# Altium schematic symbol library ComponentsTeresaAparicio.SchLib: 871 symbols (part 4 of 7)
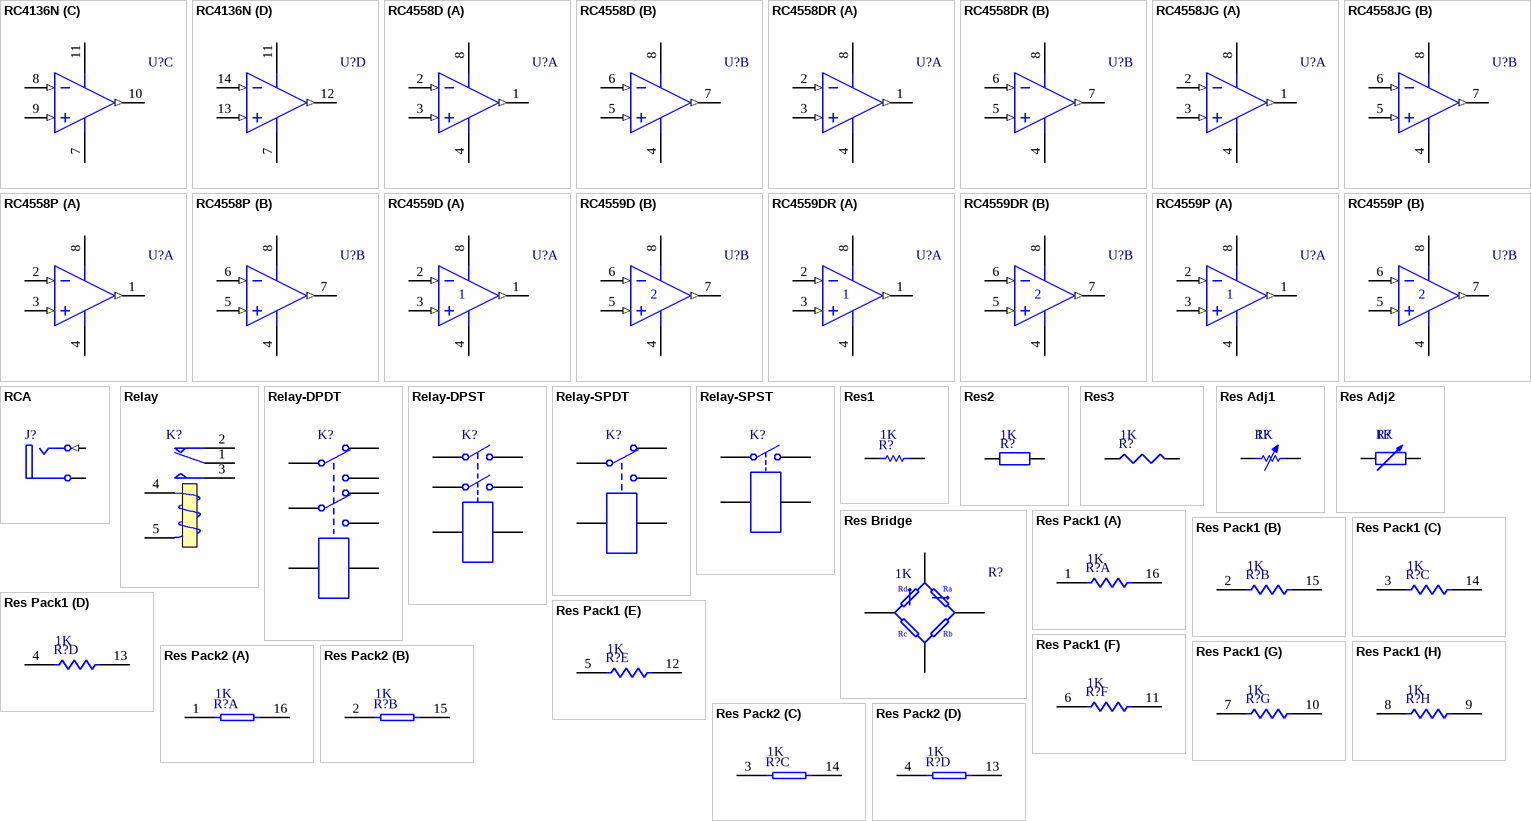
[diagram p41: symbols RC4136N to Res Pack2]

## RC4558P
designator U?
Dual High-Performance Operational Amplifier
footprint P008 (DIP; 8 Leads; Row Spacing 7.62 mm; Pitch 2.54 mm)
3D model P008 (DIP; 8 Leads; Row Spacing 7.62 mm; Pitch 2.54 mm)
pins on every part: 4 V- (power), 8 V+ (power)
part A pins: 1 OUT (out), 2 IN- (in), 3 IN+ (in)
part B pins: 5 IN+ (in), 6 IN- (in), 7 OUT (out)

## RC4559D
designator U?
Dual High-Performance Operational Amplifier
footprint D008_L (SOIC, 8-Leads, Body 4.9x3.9mm, Pitch 1.27mm, IPC High Density)
footprint D008_M (SOIC, 8-Leads, Body 4.9x3.9mm, Pitch 1.27mm, IPC Low Density)
footprint D008_M (SOIC, 8-Leads, Body 4.9x3.9mm, Pitch 1.27mm, IPC Low Density)
3D model D008 (8-Pin Small Outline Integrated Circuit 1.27 mm Pitch)
pins on every part: 4 V- (power), 8 V+ (power)
part A pins: 1 OUT (out), 2 IN- (in), 3 IN+ (in)
part B pins: 5 IN+ (in), 6 IN- (in), 7 OUT (out)

## RC4559DR
designator U?
Dual High-Performance Operational Amplifier
footprint D008_L (SOIC, 8-Leads, Body 4.9x3.9mm, Pitch 1.27mm, IPC High Density)
footprint D008_M (SOIC, 8-Leads, Body 4.9x3.9mm, Pitch 1.27mm, IPC Low Density)
footprint D008_M (SOIC, 8-Leads, Body 4.9x3.9mm, Pitch 1.27mm, IPC Low Density)
3D model D008 (8-Pin Small Outline Integrated Circuit 1.27 mm Pitch)
pins on every part: 4 V- (power), 8 V+ (power)
part A pins: 1 OUT (out), 2 IN- (in), 3 IN+ (in)
part B pins: 5 IN+ (in), 6 IN- (in), 7 OUT (out)

## RC4559P
designator U?
Dual High-Performance Operational Amplifier
footprint P008 (DIP; 8 Leads; Row Spacing 7.62 mm; Pitch 2.54 mm)
3D model P008 (DIP; 8 Leads; Row Spacing 7.62 mm; Pitch 2.54 mm)
pins on every part: 4 V- (power), 8 V+ (power)
part A pins: 1 OUT (out), 2 IN- (in), 3 IN+ (in)
part B pins: 5 IN+ (in), 6 IN- (in), 7 OUT (out)

## RCA
designator J?
RCA Phono Jack, Right Angle, Thru-Hole, Snap-In; PCB_Layout: Complies with manufacturer's recommendation.; DrillAndSlotSize: Corresponds to nominal value.
footprint RCA/4.5-H2 (Two Conductor Jack (RCA), Right Angle, Thru-Hole, Body 10 x 10 x 13 mm (WxTxH))
signal-integrity model RCA
pins: 1A Ground (power) "Outer Shield (Sleeve)", 2B Signal (in) "Center Pin (Plug Tip)"

## Relay
designator K?
SPDT Relay
footprint MODULE5B (DIP; 5 Round Pins; Row Space 15.24 mm; Pitch 2.54 mm)
simulation model SPDTRELAY (Spice Subcircuit)
pins: 1 COM, 2 NC, 3 NO, 4 T1, 5 T2

## Relay-DPDT
designator K?
Dual-Pole Dual-Throw Relay
footprint DIP-P8 (Dual-Pole Dual-Throw Relay; 8 Leads)
simulation model DPDTRELAY (Spice Subcircuit)
pins: 1, 2, 3, 4, 5, 6, 7, 8

## Relay-DPST
designator K?
Dual-Pole Single-Throw Relay
footprint MODULE6 (DIP; 6 Round Pins; Row Space 20.32 mm; Pitch 2.54 mm)
simulation model DPSTRELAY (Spice Subcircuit)
pins: 1, 2, 3, 4, 5, 6

## Relay-SPDT
designator K?
Single-Pole Dual-Throw Relay
footprint MODULE5B (DIP; 5 Round Pins; Row Space 15.24 mm; Pitch 2.54 mm)
simulation model SPDTRELAY (Spice Subcircuit)
pins: 1, 2, 3, 4, 5

## Relay-SPST
designator K?
Single-Pole Single-Throw Relay
footprint MODULE4 (DIP; 4 Round Pins; Row Space 27.94 mm; Pitch 15.24 mm)
simulation model SPSTRELAY (Spice Subcircuit)
pins: 1, 2, 3, 4

## Res1
designator R?  value 1K
Resistor
footprint AXIAL-0.3 (Axial Device, Thru-Hole; 2 Leads; 0.3 in Pin Spacing)
simulation model RESISTOR (Resistor)
signal-integrity model Res
pins: 1, 2

## Res2
designator R?  value 1K
Resistor
footprint AXIAL-0.4 (Axial Device, Thru-Hole; 2 Leads; 0.4 in Pin Spacing)
simulation model RESISTOR (Resistor)
signal-integrity model Res
pins: 1, 2

## Res3
designator R?  value 1K
Resistor
footprint J1-0603 (Chip Resistor, Body 1.6x0.8mm, IPC High Density)
footprint 14-1210 (Chip Resistor, Body 3.2x2.5mm, IPC High Density)
footprint 12Z-2010 (Chip Resistor, Body 5.0x2.5mm, IPC High Density)
footprint RESC6332 (Chip Resistor, Body 6.3x3.2mm, IPC High Density)
simulation model RESISTOR (Resistor)
signal-integrity model Res
pins: 1, 2

## Res Adj1
designator R?  value 1K
Variable Resistor; Set Position: 0.5
footprint AXIAL-0.7 (Axial Device, Thru-Hole; 2 Leads; 0.7 in Pin Spacing)
simulation model VRES (Variable Resistor)
signal-integrity model Res Adj
pins: 1, 2

## Res Adj2
designator R?  value 1K
Variable Resistor; Set Position: 0.5
footprint Pot_10mm (Can; 3 Leads; Pin Circle Dia. 2.54 mm; Lead Dia. 0.48 mm (max))
simulation model VRES (Variable Resistor)
signal-integrity model Res Adj
pins: 2, 3

## Res Bridge
designator R?  value 1K
Resistor Bridge
footprint P04A (TO, Thru-Hole, Vertical, Heatsink Mounted; 4 In-Line Leads; Pitch 2.54 mm)
signal-integrity model Res Bridge
pins: 1, 2, 3, 4

## Res Pack1
designator R?  value 1K
Isolated Resistor Network - Parts; Sim Note: Enter the Resistance value into parameter field.
footprint SOIC16_N (SOIC, 16-Leads, Body 9.9x3.9mm, Pitch 1.27mm, IPC Medium Density)
footprint SOIC16_L (SOIC, 16-Leads, Body 9.9x3.9mm, Pitch 1.27mm, IPC High Density)
footprint SOIC16_M (SOIC, 16-Leads, Body 9.9x3.9mm, Pitch 1.27mm, IPC Low Density)
simulation model RESISTOR (Resistor)
signal-integrity model Res Pack
part A pins: 1, 16
part B pins: 2, 15
part C pins: 3, 14
part D pins: 4, 13
part E pins: 5, 12
part F pins: 6, 11
part G pins: 7, 10
part H pins: 8, 9

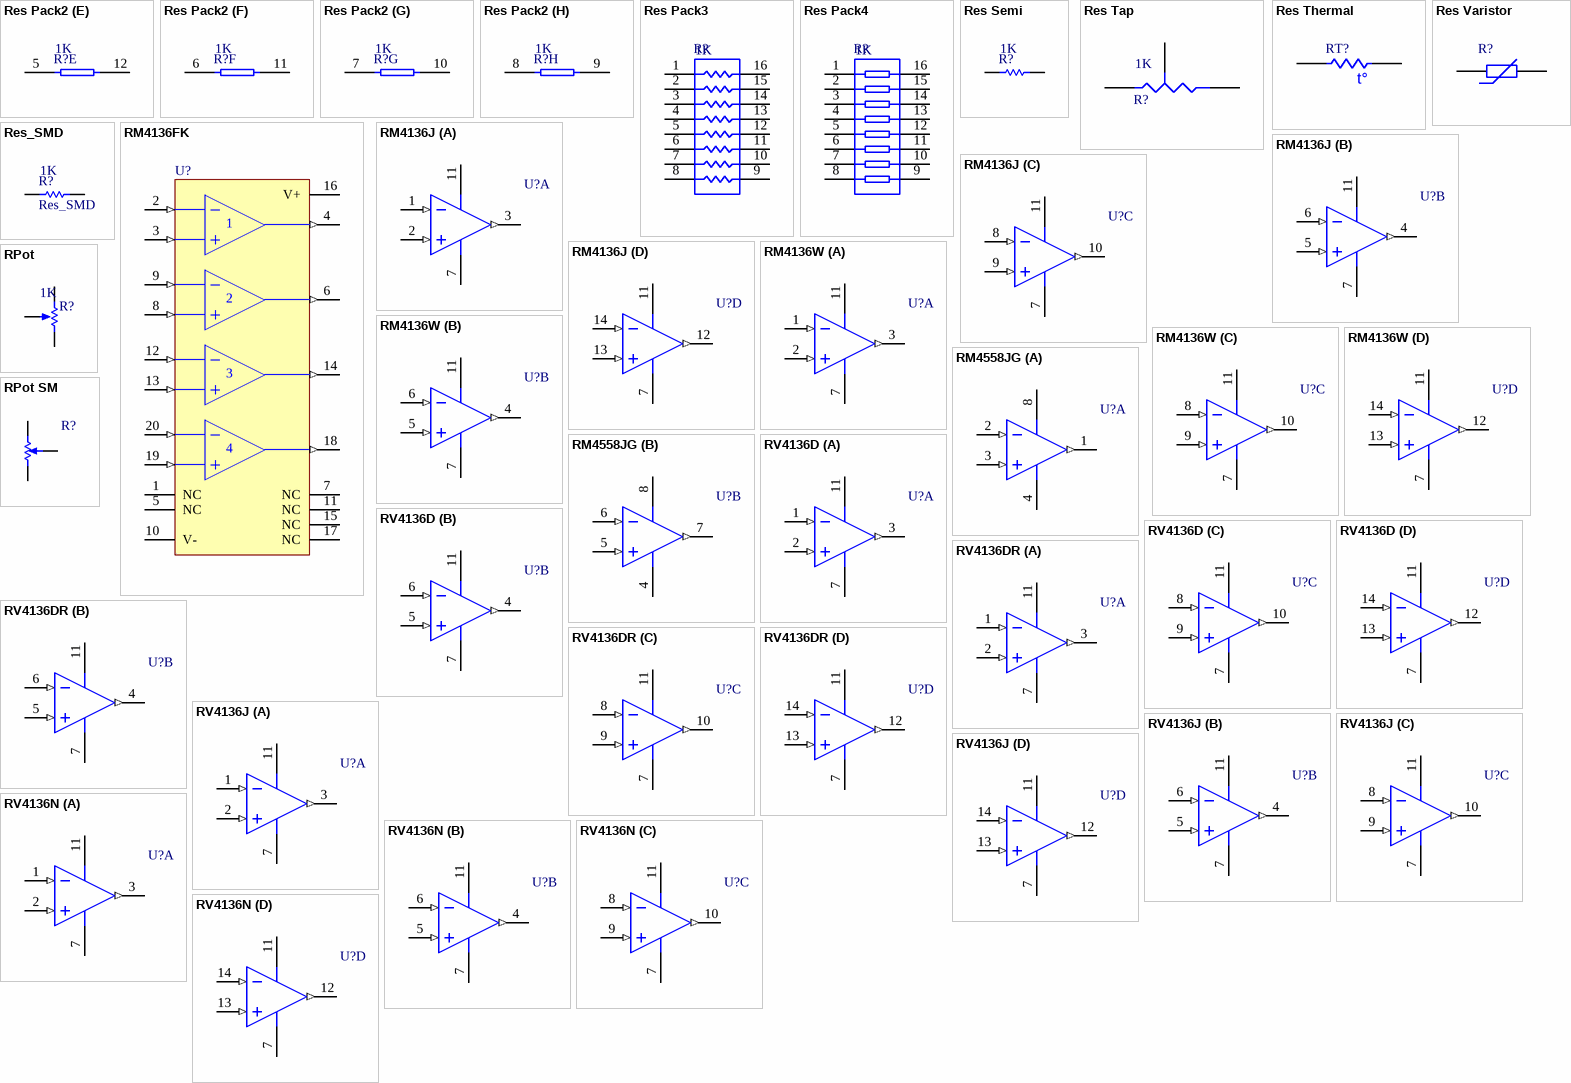
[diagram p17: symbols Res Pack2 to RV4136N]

## Res Pack2
designator R?  value 1K
Isolated Resistor Network - Parts; Sim Note: Enter the Resistance value into parameter field.
footprint DIP-16 (DIP; 16 Leads; Row Spacing 7.62 mm; Pitch 2.54 mm)
simulation model RESISTOR (Resistor)
signal-integrity model Res Pack
part A pins: 1, 16
part B pins: 2, 15
part C pins: 3, 14
part D pins: 4, 13
part E pins: 5, 12
part F pins: 6, 11
part G pins: 7, 10
part H pins: 8, 9

## Res Pack3
designator R?  value 1K
Isolated Resistor Network
footprint SO-16_N (SOIC, 16-Leads, Body 9.9x3.9mm, Pitch 1.27mm, IPC Medium Density)
footprint SO-16_L (SOIC, 16-Leads, Body 9.9x3.9mm, Pitch 1.27mm, IPC High Density)
footprint SO-16_M (SOIC, 16-Leads, Body 9.9x3.9mm, Pitch 1.27mm, IPC Low Density)
simulation model respack_8 (Spice Subcircuit)
pins: 1, 2, 3, 4, 5, 6, 7, 8, 9, 10, 11, 12, 13, 14, 15, 16

## Res Pack4
designator R?  value 1K
Isolated Resistor Network
footprint SSOP16_N (SOP, 16-Leads, Body 6.2x5.3mm, Pitch 0.65mm, IPC Medium Density)
footprint SSOP16_L (SOP, 16-Leads, Body 6.2x5.3mm, Pitch 0.65mm, IPC High Density)
footprint SSOP16_M (SOP, 16-Leads, Body 6.2x5.3mm, Pitch 0.65mm, IPC Low Density)
simulation model respack_8 (Spice Subcircuit)
pins: 1, 2, 3, 4, 5, 6, 7, 8, 9, 10, 11, 12, 13, 14, 15, 16

## Res Semi
designator R?  value 1K
Semiconductor Resistor
footprint AXIAL-0.5 (Axial Device, Thru-Hole; 2 Leads; 0.5 in Pin Spacing)
simulation model RES (Semiconductor Resistor)
signal-integrity model Res Semi
pins: 1, 2

## Res Tap
designator R?  value 1K
Tapped Resistor; Sim Note: Enter the Resistance value and the set point into parameter fields.; Set Position: 0.5
footprint VR3 (Thru-Hole; 3 Leads)
simulation model POT (Potentiometer)
signal-integrity model Res Tap
pins: 1 A, 2 B, 3 TAP

## Res Thermal
designator RT?
Thermistor
footprint 6-0805_N (Chip Resistor, Body 2.0x1.2mm, IPC Medium Density)
footprint 6-0805_L (Chip Resistor, Body 2.0x1.2mm, IPC High Density)
footprint 6-0805_M (Chip Resistor, Body 2.0x1.2mm, IPC Low Density)
pins: 1, 2

## Res Varistor
designator R?
Varistor (Voltage-Sensitive Resistor)
footprint 6-0805_N (Chip Resistor, Body 2.0x1.2mm, IPC Medium Density)
footprint 6-0805_L (Chip Resistor, Body 2.0x1.2mm, IPC High Density)
footprint 6-0805_M (Chip Resistor, Body 2.0x1.2mm, IPC Low Density)
pins: 1, 2

## Res_SMD
designator R?  value 1K
Resistor
footprint ERA-0805 (Chip Resistor; Body 2 x 1.3 mm (LxW typ))
simulation model RESISTOR (Resistor)
signal-integrity model 0805
pins: 1, 2

## RM4136FK
designator U?
Quad High-Performance Operational Amplifier
footprint FK020 (Leadless Chip Carrier; 20 Terminals; Body 8.9 x 8.9 mm)
pins: 1 NC, 2 IN- (in), 3 IN+ (in), 4 OUT (out), 5 NC, 6 OUT (out), 7 NC, 8 IN+ (in), 9 IN- (in), 10 V- (power), 11 NC, 12 IN- (in), 13 IN+ (in), 14 OUT (out), 15 NC, 16 V+ (power), 17 NC, 18 OUT (out), 19 IN+ (in), 20 IN- (in)

## RM4136J
designator U?
Quad High-Performance Operational Amplifier
footprint J014 (DIP; 14 Leads; Row Spacing 7.62 mm; Pitch 2.54 mm)
3D model J014 (DIP; 14 Leads; Row Spacing 7.62 mm; Pitch 2.54 mm)
pins on every part: 7 V- (power), 11 V+ (power)
part A pins: 1 IN- (in), 2 IN+ (in), 3 OUT (out)
part B pins: 4 OUT (out), 5 IN+ (in), 6 IN- (in)
part C pins: 8 IN- (in), 9 IN+ (in), 10 OUT (out)
part D pins: 12 OUT (out), 13 IN+ (in), 14 IN- (in)

## RM4136W
designator U?
Quad High-Performance Operational Amplifier
footprint W014 (DFP; 14 Leads; Body 9.9 x 6.6 mm (LxW max); Pitch 1.27 mm)
3D model W014 (DFP; 14 Leads; Body 9.9 x 6.6 mm (LxW max); Pitch 1.27 mm)
pins on every part: 7 V- (power), 11 V+ (power)
part A pins: 1 IN- (in), 2 IN+ (in), 3 OUT (out)
part B pins: 4 OUT (out), 5 IN+ (in), 6 IN- (in)
part C pins: 8 IN- (in), 9 IN+ (in), 10 OUT (out)
part D pins: 12 OUT (out), 13 IN+ (in), 14 IN- (in)

## RM4558JG
designator U?
Dual High-Performance Operational Amplifier
footprint JG008 (DIP; 8 Leads; Row Spacing 7.62 mm; Pitch 2.54 mm)
3D model JG008 (DIP; 8 Leads; Row Spacing 7.62 mm; Pitch 2.54 mm)
pins on every part: 4 V- (power), 8 V+ (power)
part A pins: 1 OUT (out), 2 IN- (in), 3 IN+ (in)
part B pins: 5 IN+ (in), 6 IN- (in), 7 OUT (out)

## RPot
designator R?  value 1K
Potentiometer; Sim Note: Enter the Resistance value and the set point into parameter fields.; Set Position: 0.5
footprint VR5 (Thru-Hole; 3 Leads)
simulation model POT (Potentiometer)
pins: 1 TOP, 2 BOT, 3 TAP
1 alternate drawing of the same symbol

## RPot SM
designator R?
Square Trimming Potentiometer
footprint POT4MM-2 (Square Trimming Potentiometer)
pins: CCW -, CW +, W
1 alternate drawing of the same symbol

## RV4136D
designator U?
Quad High-Performance Operational Amplifier
footprint D014_N (SOIC, 14-Leads, Body 8.7x3.9mm, Pitch 1.27mm, IPC Medium Density)
footprint D014_L (SOIC, 14-Leads, Body 8.7x3.9mm, Pitch 1.27mm, IPC High Density)
footprint D014_M (SOIC, 14-Leads, Body 8.7x3.9mm, Pitch 1.27mm, IPC Low Density)
3D model D014 (14-Pin Small Outline Integrated Circuit 1.27 mm Pitch)
pins on every part: 7 V- (power), 11 V+ (power)
part A pins: 1 IN- (in), 2 IN+ (in), 3 OUT (out)
part B pins: 4 OUT (out), 5 IN+ (in), 6 IN- (in)
part C pins: 8 IN- (in), 9 IN+ (in), 10 OUT (out)
part D pins: 12 OUT (out), 13 IN+ (in), 14 IN- (in)

## RV4136DR
designator U?
Quad High-Performance Operational Amplifier
footprint D014_N (SOIC, 14-Leads, Body 8.7x3.9mm, Pitch 1.27mm, IPC Medium Density)
footprint D014_L (SOIC, 14-Leads, Body 8.7x3.9mm, Pitch 1.27mm, IPC High Density)
footprint D014_M (SOIC, 14-Leads, Body 8.7x3.9mm, Pitch 1.27mm, IPC Low Density)
3D model D014 (14-Pin Small Outline Integrated Circuit 1.27 mm Pitch)
pins on every part: 7 V- (power), 11 V+ (power)
part A pins: 1 IN- (in), 2 IN+ (in), 3 OUT (out)
part B pins: 4 OUT (out), 5 IN+ (in), 6 IN- (in)
part C pins: 8 IN- (in), 9 IN+ (in), 10 OUT (out)
part D pins: 12 OUT (out), 13 IN+ (in), 14 IN- (in)

## RV4136J
designator U?
Quad High-Performance Operational Amplifier
footprint J014 (DIP; 14 Leads; Row Spacing 7.62 mm; Pitch 2.54 mm)
3D model J014 (DIP; 14 Leads; Row Spacing 7.62 mm; Pitch 2.54 mm)
pins on every part: 7 V- (power), 11 V+ (power)
part A pins: 1 IN- (in), 2 IN+ (in), 3 OUT (out)
part B pins: 4 OUT (out), 5 IN+ (in), 6 IN- (in)
part C pins: 8 IN- (in), 9 IN+ (in), 10 OUT (out)
part D pins: 12 OUT (out), 13 IN+ (in), 14 IN- (in)

## RV4136N
designator U?
Quad High-Performance Operational Amplifier; ComponentAvailability: Obsolete
footprint N014 (DIP; 14 Leads; Row Spacing 7.62 mm; Pitch 2.54 mm)
3D model N014 (DIP; 14 Leads; Row Spacing 7.62 mm; Pitch 2.54 mm)
pins on every part: 7 V- (power), 11 V+ (power)
part A pins: 1 IN- (in), 2 IN+ (in), 3 OUT (out)
part B pins: 4 OUT (out), 5 IN+ (in), 6 IN- (in)
part C pins: 8 IN- (in), 9 IN+ (in), 10 OUT (out)
part D pins: 12 OUT (out), 13 IN+ (in), 14 IN- (in)

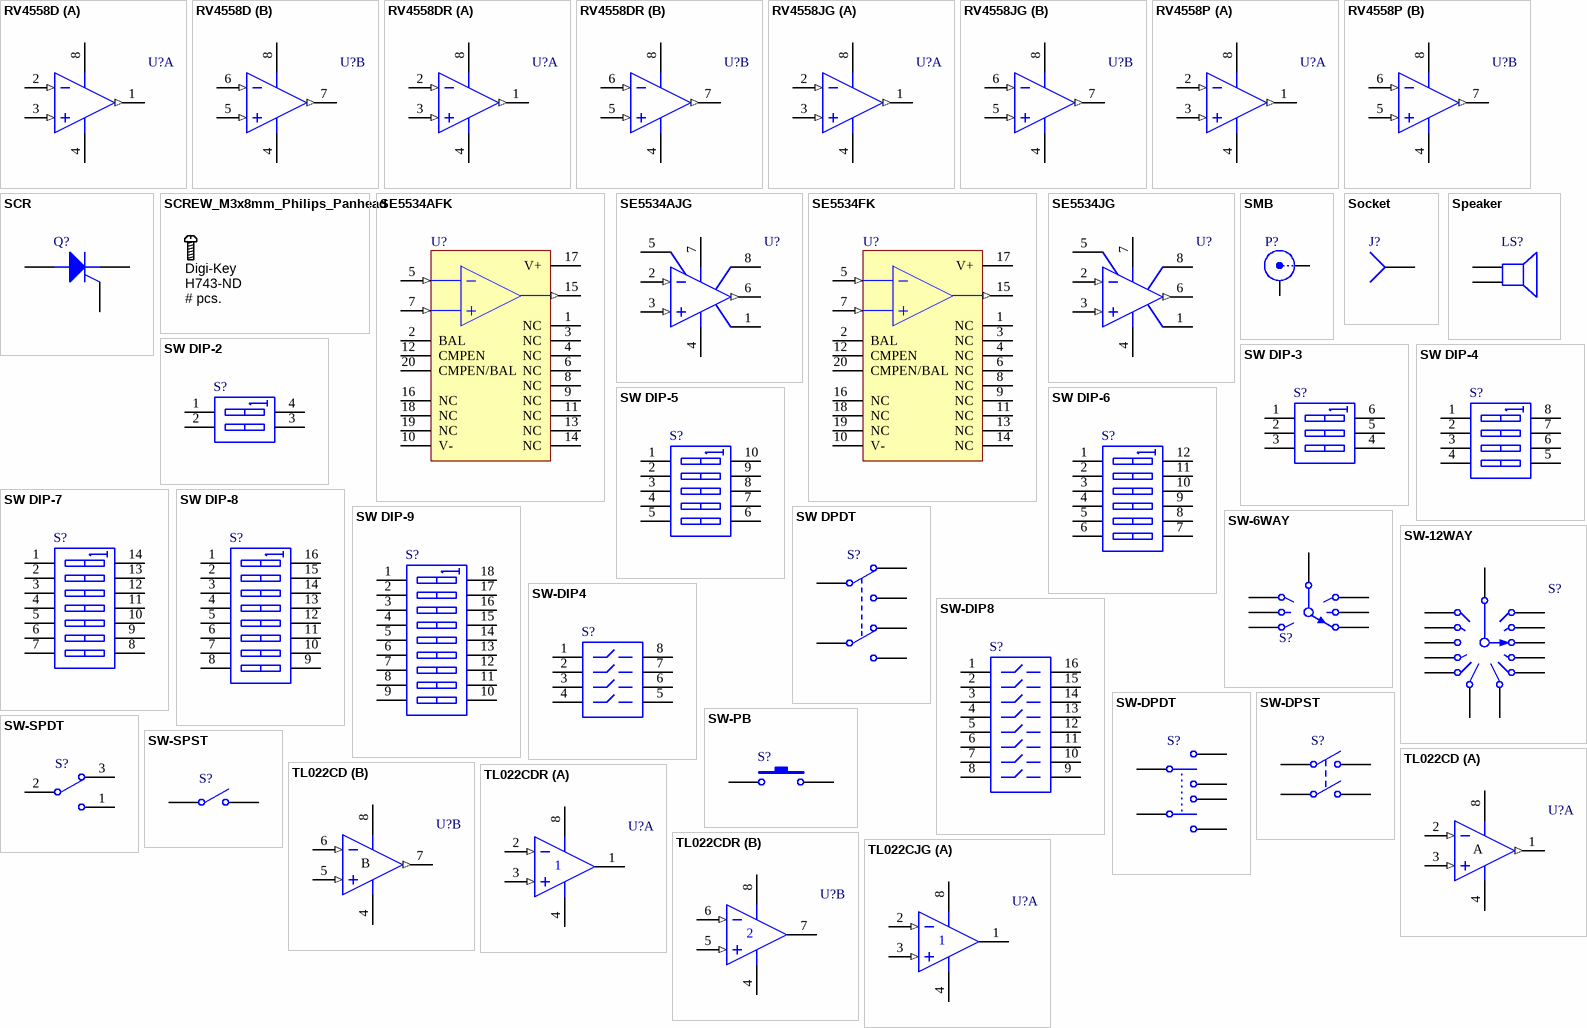
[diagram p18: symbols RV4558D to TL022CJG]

## RV4558D
designator U?
Dual High-Performance Operational Amplifier; ComponentAvailability: Obsolete
footprint D008_L (SOIC, 8-Leads, Body 4.9x3.9mm, Pitch 1.27mm, IPC High Density)
footprint D008_M (SOIC, 8-Leads, Body 4.9x3.9mm, Pitch 1.27mm, IPC Low Density)
footprint D008_M (SOIC, 8-Leads, Body 4.9x3.9mm, Pitch 1.27mm, IPC Low Density)
3D model D008 (8-Pin Small Outline Integrated Circuit 1.27 mm Pitch)
pins on every part: 4 V- (power), 8 V+ (power)
part A pins: 1 OUT (out), 2 IN- (in), 3 IN+ (in)
part B pins: 5 IN+ (in), 6 IN- (in), 7 OUT (out)

## RV4558DR
designator U?
Dual High-Performance Operational Amplifier; ComponentAvailability: Obsolete
footprint D008_L (SOIC, 8-Leads, Body 4.9x3.9mm, Pitch 1.27mm, IPC High Density)
footprint D008_M (SOIC, 8-Leads, Body 4.9x3.9mm, Pitch 1.27mm, IPC Low Density)
footprint D008_M (SOIC, 8-Leads, Body 4.9x3.9mm, Pitch 1.27mm, IPC Low Density)
3D model D008 (8-Pin Small Outline Integrated Circuit 1.27 mm Pitch)
pins on every part: 4 V- (power), 8 V+ (power)
part A pins: 1 OUT (out), 2 IN- (in), 3 IN+ (in)
part B pins: 5 IN+ (in), 6 IN- (in), 7 OUT (out)

## RV4558JG
designator U?
Dual High-Performance Operational Amplifier
footprint JG008 (DIP; 8 Leads; Row Spacing 7.62 mm; Pitch 2.54 mm)
3D model JG008 (DIP; 8 Leads; Row Spacing 7.62 mm; Pitch 2.54 mm)
pins on every part: 4 V- (power), 8 V+ (power)
part A pins: 1 OUT (out), 2 IN- (in), 3 IN+ (in)
part B pins: 5 IN+ (in), 6 IN- (in), 7 OUT (out)

## RV4558P
designator U?
Dual High-Performance Operational Amplifier; ComponentAvailability: Obsolete
footprint P008 (DIP; 8 Leads; Row Spacing 7.62 mm; Pitch 2.54 mm)
3D model P008 (DIP; 8 Leads; Row Spacing 7.62 mm; Pitch 2.54 mm)
pins on every part: 4 V- (power), 8 V+ (power)
part A pins: 1 OUT (out), 2 IN- (in), 3 IN+ (in)
part B pins: 5 IN+ (in), 6 IN- (in), 7 OUT (out)

## SCR
designator Q?
Silicon Controlled Rectifier
footprint TO-220-AB (TO, Thru-Hole, Vertical, Heatsink Mounted; 3 In-Line Leads; Pitch 2.54 mm)
simulation model SCR (Spice Subcircuit)
pins: 1 A, 2 G, 3 K

## SCREW_M3x8mm_Philips_Panhead
designator *, comment # pcs.  Supplier 1: Digi-Key  Supplier Part Number 1: H743-ND  (mechanical)
SCREW MACHINE METRIC PH M3X8MM; Manufacturer 1: B&F Fastener Supply; Manufacturer Part Number 1: MPMS 003 0008 PH; Screw Head Type: Phillips Panhead; Thread Size: M3; Head Height: 0.090" (2.29mm); Plating: Zinc; SCDType: undef
footprint Screw

## SE5534AFK
designator U?
Low-Noise Operational Amplifier
footprint FK020 (Leadless Chip Carrier; 20 Terminals; Body 8.9 x 8.9 mm)
pins: 1 NC, 2 BAL, 3 NC, 4 NC, 5 IN- (in), 6 NC, 7 IN+ (in), 8 NC, 9 NC, 10 V- (power), 11 NC, 12 CMPEN, 13 NC, 14 NC, 15 OUT (out), 16 NC, 17 V+ (power), 18 NC, 19 NC, 20 CMPEN/BAL

## SE5534AJG
designator U?
Low-Noise Operational Amplifier
footprint JG008 (DIP; 8 Leads; Row Spacing 7.62 mm; Pitch 2.54 mm)
3D model JG008 (DIP; 8 Leads; Row Spacing 7.62 mm; Pitch 2.54 mm)
pins: 1 BAL, 2 IN- (in), 3 IN+ (in), 4 V- (power), 5 CMPEN, 6 OUT (out), 7 V+ (power), 8 COMP/BAL

## SE5534FK
designator U?
Low-Noise Operational Amplifier
footprint FK020 (Leadless Chip Carrier; 20 Terminals; Body 8.9 x 8.9 mm)
pins: 1 NC, 2 BAL, 3 NC, 4 NC, 5 IN- (in), 6 NC, 7 IN+ (in), 8 NC, 9 NC, 10 V- (power), 11 NC, 12 CMPEN, 13 NC, 14 NC, 15 OUT (out), 16 NC, 17 V+ (power), 18 NC, 19 NC, 20 CMPEN/BAL

## SE5534JG
designator U?
Low-Noise Operational Amplifier
footprint JG008 (DIP; 8 Leads; Row Spacing 7.62 mm; Pitch 2.54 mm)
3D model JG008 (DIP; 8 Leads; Row Spacing 7.62 mm; Pitch 2.54 mm)
pins: 1 BAL, 2 IN- (in), 3 IN+ (in), 4 V- (power), 5 CMPEN, 6 OUT (out), 7 V+ (power), 8 COMP/BAL

## SMB
designator P?
SMB Straight Connector
footprint SMB_V-RJ45 (Connector; SMB Straight)
signal-integrity model Connector
pins: 1 X, 2 Y

## Socket
designator J?
Socket
footprint PIN1 (Connector; Socket)
signal-integrity model Connector
pins: 1

## Speaker
designator LS?
Loudspeaker
footprint PIN2 (Loudspeaker; 2 Leads)
pins: 1, 2

## SW DIP-2
designator S?
DIP Switch, 2 Position, SPST
footprint DIP-4 (DIP; 4 Leads; Row Spacing 7.62 mm; Pitch 2.54 mm)
simulation model dpsw2 (Spice Subcircuit)
pins: 1 A1, 2 A2, 3 B2, 4 B1

## SW DIP-3
designator S?
DIP Switch, 3 Position, SPST
footprint DIP-6 (DIP; 6 Leads; Row Spacing 7.62 mm; Pitch 2.54 mm)
simulation model dpsw3 (Spice Subcircuit)
pins: 1 A1, 2 A2, 3 A3, 4 B3, 5 B2, 6 B1

## SW DIP-4
designator S?
DIP Switch, 4 Position, SPST
footprint SO8_N (SOIC, 8-Leads, Body 4.9x3.9mm, Pitch 1.27mm, IPC Medium Density)
footprint SO8_L (SOIC, 8-Leads, Body 4.9x3.9mm, Pitch 1.27mm, IPC High Density)
footprint SO8_M (SOIC, 8-Leads, Body 4.9x3.9mm, Pitch 1.27mm, IPC Low Density)
simulation model dpsw4 (Spice Subcircuit)
pins: 1 A1, 2 A2, 3 A3, 4 A4, 5 B4, 6 B3, 7 B2, 8 B1

## SW DIP-5
designator S?
DIP Switch, 5 Position, SPST
footprint N10A (DIP; 10 Leads; Row Spacing 7.62 mm; Pitch 2.54 mm)
simulation model dpsw5 (Spice Subcircuit)
pins: 1 A1, 2 A2, 3 A3, 4 A4, 5 A5, 6 B5, 7 B4, 8 B3, 9 B2, 10 B1

## SW DIP-6
designator S?
DIP Switch, 6 Position, SPST
footprint DIP-12/SW (DIP Switch; 12 Leads)
simulation model dpsw6 (Spice Subcircuit)
pins: 1 A1, 2 A2, 3 A3, 4 A4, 5 A5, 6 A6, 7 B6, 8 B5, 9 B4, 10 B3, 11 B2, 12 B1

## SW DIP-7
designator S?
DIP Switch, 7 Position, SPST
footprint DIP-14 (DIP; 14 Leads; Row Spacing 7.62 mm; Pitch 2.54 mm)
simulation model dpsw7 (Spice Subcircuit)
pins: 1 A1, 2 A2, 3 A3, 4 A4, 5 A5, 6 A6, 7 A7, 8 B7, 9 B6, 10 B5, 11 B4, 12 B3, 13 B2, 14 B1

## SW DIP-8
designator S?
DIP Switch, 8 Position, SPST
footprint DIP_SW_8WAY_SMD (DIP Switch; 16 Leads)
simulation model dpsw8 (Spice Subcircuit)
pins: 1 A1, 2 A2, 3 A3, 4 A4, 5 A5, 6 A6, 7 A7, 8 A8, 9 B8, 10 B7, 11 B6, 12 B5, 13 B4, 14 B3, 15 B2, 16 B1

## SW DIP-9
designator S?
DIP Switch, 9 Position, SPST
footprint DIP-18 (DIP; 18 Leads; Row Spacing 7.62 mm; Pitch 2.54 mm)
simulation model dpsw9 (Spice Subcircuit)
pins: 1 A1, 2 A2, 3 A3, 4 A4, 5 A5, 6 A6, 7 A7, 8 A8, 9 A9, 10 B9, 11 B8, 12 B7, 13 B6, 14 B5, 15 B4, 16 B3, 17 B2, 18 B1

## SW DPDT
designator S?
Switch
footprint SOT23-6_N (SOT23, 6-Leads, Body 2.9x1.6mm, Pitch 0.95mm, Lead Span 2.7mm, IPC Medium Density)
footprint SOT23-6_L (SOT23, 6-Leads, Body 2.9x1.6mm, Pitch 0.95mm, Lead Span 2.7mm, IPC High Density)
footprint SOT23-6_M (SOT23, 6-Leads, Body 2.9x1.6mm, Pitch 0.95mm, Lead Span 2.7mm, IPC Low Density)
pins: 1 COMMON1, 2 NC1, 3 NO1, 4 NC2, 5 COMMON2, 6 NO2

## SW-6WAY
designator S?
6 Way Switch
footprint SW-7 (Switch; 7 Leads)
pins: 1, 2, 3, 4, 5, 6, 7

## SW-12WAY
designator S?
12 Way Switch
footprint DIP-13(14) (DIP; 14 Leads (1 Absent); Row Spacing 7.62 mm; Pitch 2.54 mm)
pins: 1, 2, 3, 5, 6, 7, 8, 9, 10, 11, 12, 13, 14

## SW-DIP4
designator S?
DIP Switch
footprint DIP-8 (DIP; 8 Leads; Row Spacing 7.62 mm; Pitch 2.54 mm)
simulation model dpsw4 (Spice Subcircuit)
pins: 1, 2, 3, 4, 5, 6, 7, 8

## SW-DIP8
designator S?
4009 Series DIP Switch, Raised actuator
footprint DIP-16-KEY (DIP; 16 Leads; Row Spacing 7.62 mm; Pitch 2.54 mm)
simulation model dpsw8 (Spice Subcircuit)
pins: 1, 2, 3, 4, 5, 6, 7, 8, 9, 10, 11, 12, 13, 14, 15, 16

## SW-DPDT
designator S?
Double-Pole, Double-Throw Switch
footprint DPDT-6 (Switch; 6 Leads)
pins: 1, 2, 3, 4, 5, 6

## SW-DPST
designator S?
Double-Pole, Single-Throw Switch
footprint DPST-4 (Switch; 4 Leads)
pins: 1 COMMON1, 2 NO1, 3 COMMON2, 4 NO2

## SW-PB
designator S?
Switch
footprint SPST-2 (Switch; 2 Leads)
pins: 1, 2

## SW-SPDT
designator S?
SPDT Subminiature Toggle Switch, Right Angle Mounting, Vertical Actuation
footprint SWITCH_SPDT_SLIDER (TE Connectivity SLS121PC04 SPDT slider)
pins: 1, 2, 3

## SW-SPST
designator S?
Single-Pole, Single-Throw Switch
footprint SPST-2 (Switch; 2 Leads)
pins: 1 COMMON, 2 NO

## TL022CD
designator U?
Dual Low-Power Operational Amplifier
footprint D008_L (SOIC, 8-Leads, Body 4.9x3.9mm, Pitch 1.27mm, IPC High Density)
footprint D008_M (SOIC, 8-Leads, Body 4.9x3.9mm, Pitch 1.27mm, IPC Low Density)
footprint D008_M (SOIC, 8-Leads, Body 4.9x3.9mm, Pitch 1.27mm, IPC Low Density)
3D model D008 (8-Pin Small Outline Integrated Circuit 1.27 mm Pitch)
simulation model TL022C (SUBCKT)
pins on every part: 4 V- (power), 8 V+ (power)
part A pins: 1 OUT (out), 2 IN- (in), 3 IN+ (in)
part B pins: 5 IN+ (in), 6 IN- (in), 7 OUT (out)

## TL022CDR
designator U?
Dual Low-Power Operational Amplifier
footprint D008_L (SOIC, 8-Leads, Body 4.9x3.9mm, Pitch 1.27mm, IPC High Density)
footprint D008_M (SOIC, 8-Leads, Body 4.9x3.9mm, Pitch 1.27mm, IPC Low Density)
footprint D008_M (SOIC, 8-Leads, Body 4.9x3.9mm, Pitch 1.27mm, IPC Low Density)
3D model D008 (8-Pin Small Outline Integrated Circuit 1.27 mm Pitch)
pins on every part: 4 V- (power), 8 V+ (power)
part A pins: 1 OUT (oe), 2 IN- (in), 3 IN+ (in)
part B pins: 5 IN+ (in), 6 IN- (in), 7 OUT (oe)

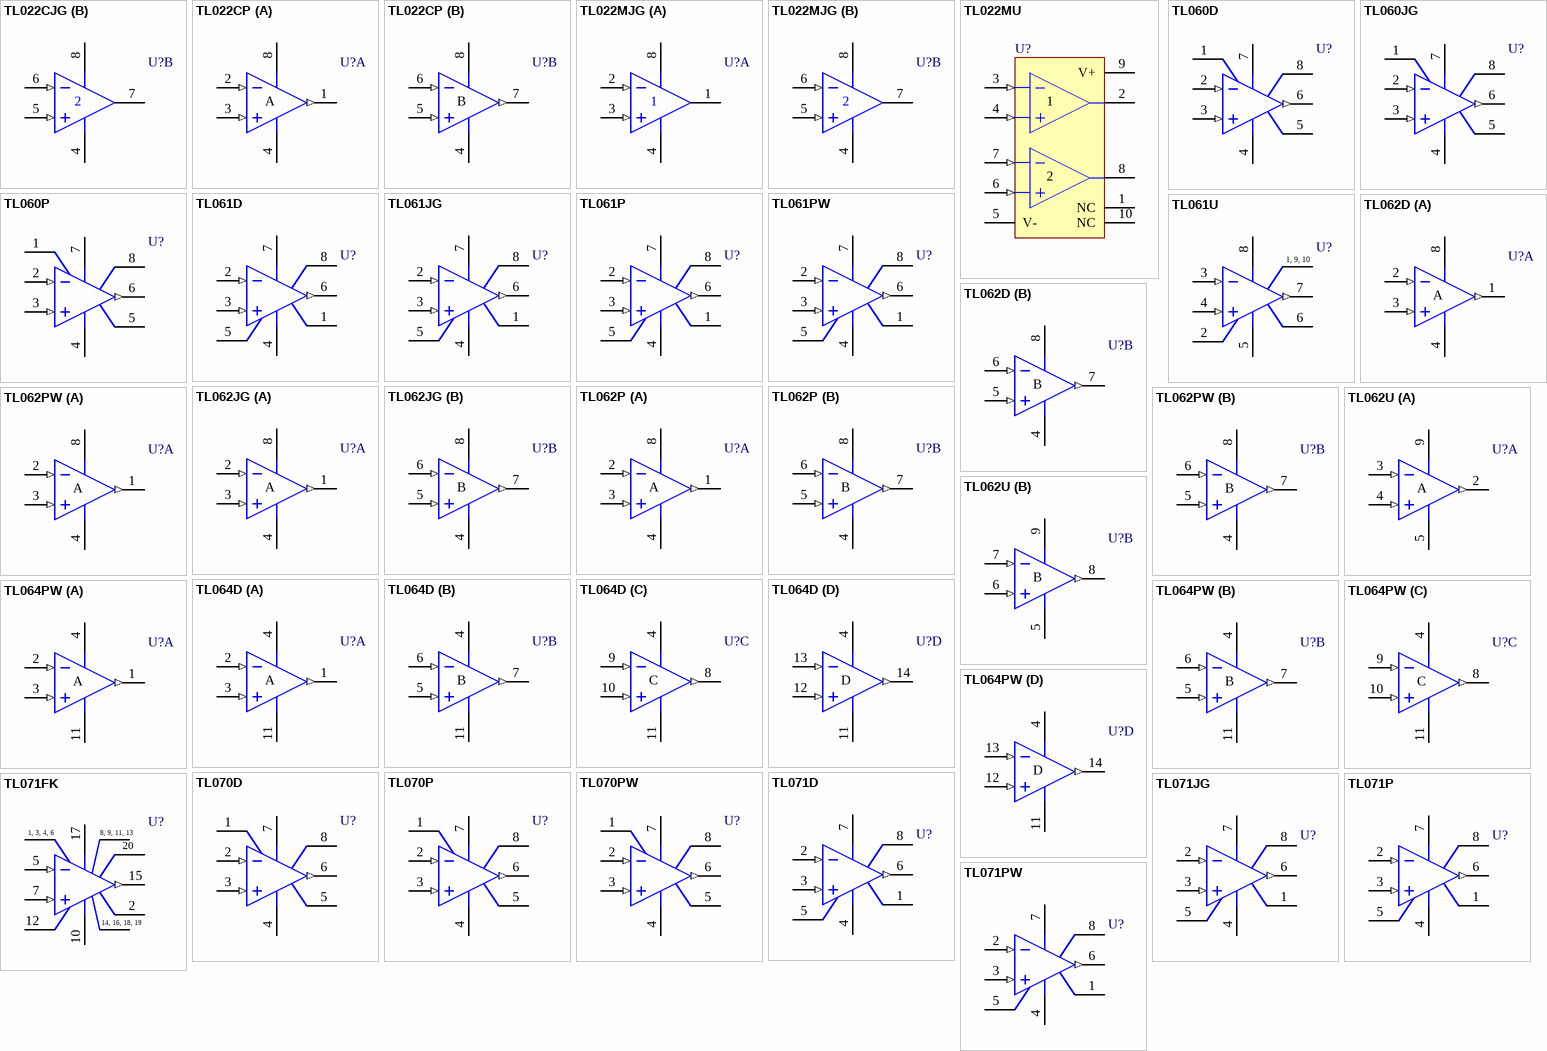
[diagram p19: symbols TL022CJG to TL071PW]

## TL022CJG
designator U?
Dual Low-Power Operational Amplifier
footprint JG008 (DIP; 8 Leads; Row Spacing 7.62 mm; Pitch 2.54 mm)
3D model JG008 (DIP; 8 Leads; Row Spacing 7.62 mm; Pitch 2.54 mm)
pins on every part: 4 V- (power), 8 V+ (power)
part A pins: 1 OUT (oe), 2 IN- (in), 3 IN+ (in)
part B pins: 5 IN+ (in), 6 IN- (in), 7 OUT (oe)

## TL022CP
designator U?
Dual Low-Power Operational Amplifier
footprint P008 (DIP; 8 Leads; Row Spacing 7.62 mm; Pitch 2.54 mm)
3D model P008 (DIP; 8 Leads; Row Spacing 7.62 mm; Pitch 2.54 mm)
simulation model TL022C (SUBCKT)
pins on every part: 4 V- (power), 8 V+ (power)
part A pins: 1 OUT (out), 2 IN- (in), 3 IN+ (in)
part B pins: 5 IN+ (in), 6 IN- (in), 7 OUT (out)

## TL022MJG
designator U?
Dual Low-Power Operational Amplifier
footprint JG008 (DIP; 8 Leads; Row Spacing 7.62 mm; Pitch 2.54 mm)
3D model JG008 (DIP; 8 Leads; Row Spacing 7.62 mm; Pitch 2.54 mm)
pins on every part: 4 V- (power), 8 V+ (power)
part A pins: 1 OUT (oe), 2 IN- (in), 3 IN+ (in)
part B pins: 5 IN+ (in), 6 IN- (in), 7 OUT (oe)

## TL022MU
designator U?
Dual Low-Power Operational Amplifier
footprint U010 (DFP; 10 Leads; Body 7.1 x 6.4 mm (LxW max); Pitch 1.27 mm)
3D model U010 (DFP; 10 Leads; Body 7.1 x 6.4 mm (LxW max); Pitch 1.27 mm)
pins: 1 NC, 2 OUT (oe), 3 IN- (in), 4 IN+ (in), 5 V- (power), 6 IN+ (in), 7 IN- (in), 8 OUT (oe), 9 V+ (power), 10 NC

## TL060D
designator U?
Low-Power JFET-Input Operational Amplifier
footprint D008_L (SOIC, 8-Leads, Body 4.9x3.9mm, Pitch 1.27mm, IPC High Density)
footprint D008_M (SOIC, 8-Leads, Body 4.9x3.9mm, Pitch 1.27mm, IPC Low Density)
footprint D008_M (SOIC, 8-Leads, Body 4.9x3.9mm, Pitch 1.27mm, IPC Low Density)
3D model D008 (8-Pin Small Outline Integrated Circuit 1.27 mm Pitch)
simulation model TL060 (SUBCKT)
pins: 1 BAL1/CMPEN, 2 IN- (in), 3 IN+ (in), 4 V- (power), 5 BAL2, 6 OUT (out), 7 V+ (power), 8 CMPEN

## TL060JG
designator U?
Low-Power JFET-Input Operational Amplifier
footprint JG008 (DIP; 8 Leads; Row Spacing 7.62 mm; Pitch 2.54 mm)
3D model JG008 (DIP; 8 Leads; Row Spacing 7.62 mm; Pitch 2.54 mm)
simulation model TL060 (SUBCKT)
pins: 1 BAL1/CMPEN, 2 IN- (in), 3 IN+ (in), 4 V- (power), 5 BAL2, 6 OUT (out), 7 V+ (power), 8 CMPEN

## TL060P
designator U?
Low-Power JFET-Input Operational Amplifier
footprint P008 (DIP; 8 Leads; Row Spacing 7.62 mm; Pitch 2.54 mm)
3D model P008 (DIP; 8 Leads; Row Spacing 7.62 mm; Pitch 2.54 mm)
simulation model TL060 (SUBCKT)
pins: 1 BAL1/CMPEN, 2 IN- (in), 3 IN+ (in), 4 V- (power), 5 BAL2, 6 OUT (out), 7 V+ (power), 8 CMPEN

## TL061D
designator U?
Low-Power JFET-Input Operational Amplifier; Note: Pin 8 is not connected
footprint D008_L (SOIC, 8-Leads, Body 4.9x3.9mm, Pitch 1.27mm, IPC High Density)
footprint D008_M (SOIC, 8-Leads, Body 4.9x3.9mm, Pitch 1.27mm, IPC Low Density)
footprint D008_M (SOIC, 8-Leads, Body 4.9x3.9mm, Pitch 1.27mm, IPC Low Density)
3D model D008 (8-Pin Small Outline Integrated Circuit 1.27 mm Pitch)
simulation model TL061 (SUBCKT)
pins: 1 OS TRIM, 2 IN- (in), 3 IN+ (in), 4 V- (power), 5 OS TRIM, 6 OUT (out), 7 V+ (power), 8 NC

## TL061JG
designator U?
Low-Power JFET-Input Operational Amplifier; Note: Pin 8 is not connected
footprint JG008 (DIP; 8 Leads; Row Spacing 7.62 mm; Pitch 2.54 mm)
3D model JG008 (DIP; 8 Leads; Row Spacing 7.62 mm; Pitch 2.54 mm)
simulation model TL061 (SUBCKT)
pins: 1 OS TRIM, 2 IN- (in), 3 IN+ (in), 4 V- (power), 5 OS TRIM, 6 OUT (out), 7 V+ (power), 8 NC

## TL061P
designator U?
Low-Power JFET-Input Operational Amplifier; Note: Pin 8 is not connected
footprint P008 (DIP; 8 Leads; Row Spacing 7.62 mm; Pitch 2.54 mm)
3D model P008 (DIP; 8 Leads; Row Spacing 7.62 mm; Pitch 2.54 mm)
simulation model TL061 (SUBCKT)
pins: 1 OS TRIM, 2 IN- (in), 3 IN+ (in), 4 V- (power), 5 OS TRIM, 6 OUT (out), 7 V+ (power), 8 NC

## TL061PW
designator U?
Low-Power JFET-Input Operational Amplifier; Note: Pin 8 is not connected
footprint PW008_N (SOP, 8-Leads, Body 3x4.4mm, Pitch 0.65mm, IPC Medium Density)
footprint PW008_L (SOP, 8-Leads, Body 3x4.4mm, Pitch 0.65mm, IPC High Density)
footprint PW008_M (SOP, 8-Leads, Body 3x4.4mm, Pitch 0.65mm, IPC Low Density)
3D model PW008 (8-Pin Small Outline Package 0.65 mm Pitch)
simulation model TL061 (SUBCKT)
pins: 1 OS TRIM, 2 IN- (in), 3 IN+ (in), 4 V- (power), 5 OS TRIM, 6 OUT (out), 7 V+ (power), 8 NC

## TL061U
designator U?
Low-Power JFET-Input Operational Amplifier; Note: Pin 1,9 and 10 are not connected
footprint U010 (DFP; 10 Leads; Body 7.1 x 6.4 mm (LxW max); Pitch 1.27 mm)
3D model U010 (DFP; 10 Leads; Body 7.1 x 6.4 mm (LxW max); Pitch 1.27 mm)
simulation model TL061 (SUBCKT)
pins: 1 NC, 2 BAL1, 3 IN- (in), 4 IN+ (in), 5 V- (power), 6 BAL2, 7 OUT (out), 8 V+ (power), 9 NC, 10 NC

## TL062D
designator U?
Low-Power JFET-Input Operational Amplifier
footprint D008_L (SOIC, 8-Leads, Body 4.9x3.9mm, Pitch 1.27mm, IPC High Density)
footprint D008_M (SOIC, 8-Leads, Body 4.9x3.9mm, Pitch 1.27mm, IPC Low Density)
footprint D008_M (SOIC, 8-Leads, Body 4.9x3.9mm, Pitch 1.27mm, IPC Low Density)
3D model D008 (8-Pin Small Outline Integrated Circuit 1.27 mm Pitch)
simulation model TL062 (SUBCKT)
pins on every part: 4 V- (power), 8 V+ (power)
part A pins: 1 OUT (out), 2 IN- (in), 3 IN+ (in)
part B pins: 5 IN+ (in), 6 IN- (in), 7 OUT (out)

## TL062JG
designator U?
Low-Power JFET-Input Operational Amplifier
footprint JG008 (DIP; 8 Leads; Row Spacing 7.62 mm; Pitch 2.54 mm)
3D model JG008 (DIP; 8 Leads; Row Spacing 7.62 mm; Pitch 2.54 mm)
simulation model TL062 (SUBCKT)
pins on every part: 4 V- (power), 8 V+ (power)
part A pins: 1 OUT (out), 2 IN- (in), 3 IN+ (in)
part B pins: 5 IN+ (in), 6 IN- (in), 7 OUT (out)

## TL062P
designator U?
Low-Power JFET-Input Operational Amplifier
footprint P008 (DIP; 8 Leads; Row Spacing 7.62 mm; Pitch 2.54 mm)
3D model P008 (DIP; 8 Leads; Row Spacing 7.62 mm; Pitch 2.54 mm)
simulation model TL062 (SUBCKT)
pins on every part: 4 V- (power), 8 V+ (power)
part A pins: 1 OUT (out), 2 IN- (in), 3 IN+ (in)
part B pins: 5 IN+ (in), 6 IN- (in), 7 OUT (out)

## TL062PW
designator U?
Low-Power JFET-Input Operational Amplifier
footprint PW008_N (SOP, 8-Leads, Body 3x4.4mm, Pitch 0.65mm, IPC Medium Density)
footprint PW008_L (SOP, 8-Leads, Body 3x4.4mm, Pitch 0.65mm, IPC High Density)
footprint PW008_M (SOP, 8-Leads, Body 3x4.4mm, Pitch 0.65mm, IPC Low Density)
3D model PW008 (8-Pin Small Outline Package 0.65 mm Pitch)
simulation model TL062 (SUBCKT)
pins on every part: 4 V- (power), 8 V+ (power)
part A pins: 1 OUT (out), 2 IN- (in), 3 IN+ (in)
part B pins: 5 IN+ (in), 6 IN- (in), 7 OUT (out)

## TL062U
designator U?
Low-Power JFET-Input Operational Amplifier; Note: Pins 1 and 10 are not connected or drawn
footprint U010 (DFP; 10 Leads; Body 7.1 x 6.4 mm (LxW max); Pitch 1.27 mm)
3D model U010 (DFP; 10 Leads; Body 7.1 x 6.4 mm (LxW max); Pitch 1.27 mm)
simulation model TL062 (SUBCKT)
pins on every part: 5 V- (power), 9 V+ (power)
part A pins: 2 OUT (out), 3 IN- (in), 4 IN+ (in)
part B pins: 6 IN+ (in), 7 IN- (in), 8 OUT (out)

## TL064D
designator U?
Low-Power JFET-Input Operational Amplifier
footprint D014_N (SOIC, 14-Leads, Body 8.7x3.9mm, Pitch 1.27mm, IPC Medium Density)
footprint D014_L (SOIC, 14-Leads, Body 8.7x3.9mm, Pitch 1.27mm, IPC High Density)
footprint D014_M (SOIC, 14-Leads, Body 8.7x3.9mm, Pitch 1.27mm, IPC Low Density)
3D model D014 (14-Pin Small Outline Integrated Circuit 1.27 mm Pitch)
simulation model TL064 (SUBCKT)
pins on every part: 4 V+ (power), 11 V- (power)
part A pins: 1 OUT (out), 2 IN- (in), 3 IN+ (in)
part B pins: 5 IN+ (in), 6 IN- (in), 7 OUT (out)
part C pins: 8 OUT (out), 9 IN- (in), 10 IN+ (in)
part D pins: 12 IN+ (in), 13 IN- (in), 14 OUT (out)

## TL064PW
designator U?
Low-Power JFET-Input Operational Amplifier
footprint PW014_N (TSOP, 14-Leads, Body 5x4.4mm, Pitch 0.65mm, IPC Medium Density)
footprint PW014_L (TSOP, 14-Leads, Body 5x4.4mm, Pitch 0.65mm, IPC High Density)
footprint PW014_M (TSOP, 14-Leads, Body 5x4.4mm, Pitch 0.65mm, IPC Low Density)
3D model PW014 (14-Pin Thin Small Outline Package 0.65 mm Pitch)
simulation model TL064 (SUBCKT)
pins on every part: 4 V+ (power), 11 V- (power)
part A pins: 1 OUT (out), 2 IN- (in), 3 IN+ (in)
part B pins: 5 IN+ (in), 6 IN- (in), 7 OUT (out)
part C pins: 8 OUT (out), 9 IN- (in), 10 IN+ (in)
part D pins: 12 IN+ (in), 13 IN- (in), 14 OUT (out)

## TL070D
designator U?
JFET-Input Operational Amplifier
footprint D008_L (SOIC, 8-Leads, Body 4.9x3.9mm, Pitch 1.27mm, IPC High Density)
footprint D008_M (SOIC, 8-Leads, Body 4.9x3.9mm, Pitch 1.27mm, IPC Low Density)
footprint D008_M (SOIC, 8-Leads, Body 4.9x3.9mm, Pitch 1.27mm, IPC Low Density)
3D model D008 (8-Pin Small Outline Integrated Circuit 1.27 mm Pitch)
simulation model TL070 (SUBCKT)
pins: 1 BAL1/CMPEN, 2 IN- (in), 3 IN+ (in), 4 V- (power), 5 BAL2, 6 OUT (out), 7 V+ (power), 8 CMPEN

## TL070P
designator U?
JFET-Input Operational Amplifier
footprint P008 (DIP; 8 Leads; Row Spacing 7.62 mm; Pitch 2.54 mm)
3D model P008 (DIP; 8 Leads; Row Spacing 7.62 mm; Pitch 2.54 mm)
simulation model TL070 (SUBCKT)
pins: 1 BAL1/CMPEN, 2 IN- (in), 3 IN+ (in), 4 V- (power), 5 BAL2, 6 OUT (out), 7 V+ (power), 8 CMPEN

## TL070PW
designator U?
JFET-Input Operational Amplifier
footprint PW008_N (SOP, 8-Leads, Body 3x4.4mm, Pitch 0.65mm, IPC Medium Density)
footprint PW008_L (SOP, 8-Leads, Body 3x4.4mm, Pitch 0.65mm, IPC High Density)
footprint PW008_M (SOP, 8-Leads, Body 3x4.4mm, Pitch 0.65mm, IPC Low Density)
3D model PW008 (8-Pin Small Outline Package 0.65 mm Pitch)
simulation model TL070 (SUBCKT)
pins: 1 BAL1/CMPEN, 2 IN- (in), 3 IN+ (in), 4 V- (power), 5 BAL2, 6 OUT (out), 7 V+ (power), 8 CMPEN

## TL071D
designator U?
Low-Noise JFET-Input Operational Amplifier; Note: Pin 8 is not connected
footprint D008_L (SOIC, 8-Leads, Body 4.9x3.9mm, Pitch 1.27mm, IPC High Density)
footprint D008_M (SOIC, 8-Leads, Body 4.9x3.9mm, Pitch 1.27mm, IPC Low Density)
footprint D008_M (SOIC, 8-Leads, Body 4.9x3.9mm, Pitch 1.27mm, IPC Low Density)
3D model D008 (8-Pin Small Outline Integrated Circuit 1.27 mm Pitch)
simulation model TL071 (SUBCKT)
pins: 1 OS TRIM, 2 IN- (in), 3 IN+ (in), 4 V- (power), 5 OS TRIM, 6 OUT (out), 7 V+ (power), 8 NC

## TL071FK
designator U?
Low-Noise JFET-Input Operational Amplifier; Note: Pins 1,3,4,6,8,9,11,14,16,18,19 and 20 are not connected
footprint FK020 (Leadless Chip Carrier; 20 Terminals; Body 8.9 x 8.9 mm)
simulation model TL071 (SUBCKT)
pins: 1 NC, 2 N1/COMP, 3 NC, 4 NC, 5 IN- (in), 6 NC, 7 IN+ (in), 8 NC, 9 NC, 10 V- (power), 11 NC, 12 N2, 13 NC, 14 NC, 15 OUT (out), 16 NC, 17 V+ (power), 18 NC, 19 NC, 20 NC

## TL071JG
designator U?
Low-Noise JFET-Input Operational Amplifier; Note: Pin 8 is not connected
footprint JG008 (DIP; 8 Leads; Row Spacing 7.62 mm; Pitch 2.54 mm)
3D model JG008 (DIP; 8 Leads; Row Spacing 7.62 mm; Pitch 2.54 mm)
simulation model TL071 (SUBCKT)
pins: 1 OS TRIM, 2 IN- (in), 3 IN+ (in), 4 V- (power), 5 OS TRIM, 6 OUT (out), 7 V+ (power), 8 NC

## TL071P
designator U?
Low-Noise JFET-Input Operational Amplifier; Note: Pin 8 is not connected
footprint P008 (DIP; 8 Leads; Row Spacing 7.62 mm; Pitch 2.54 mm)
3D model P008 (DIP; 8 Leads; Row Spacing 7.62 mm; Pitch 2.54 mm)
simulation model TL071 (SUBCKT)
pins: 1 OS TRIM, 2 IN- (in), 3 IN+ (in), 4 V- (power), 5 OS TRIM, 6 OUT (out), 7 V+ (power), 8 NC

## TL071PW
designator U?
Low-Noise JFET-Input Operational Amplifier; Note: Pin 8 is not connected
footprint PW008_N (SOP, 8-Leads, Body 3x4.4mm, Pitch 0.65mm, IPC Medium Density)
footprint PW008_L (SOP, 8-Leads, Body 3x4.4mm, Pitch 0.65mm, IPC High Density)
footprint PW008_M (SOP, 8-Leads, Body 3x4.4mm, Pitch 0.65mm, IPC Low Density)
3D model PW008 (8-Pin Small Outline Package 0.65 mm Pitch)
simulation model TL071 (SUBCKT)
pins: 1 OS TRIM, 2 IN- (in), 3 IN+ (in), 4 V- (power), 5 OS TRIM, 6 OUT (out), 7 V+ (power), 8 NC

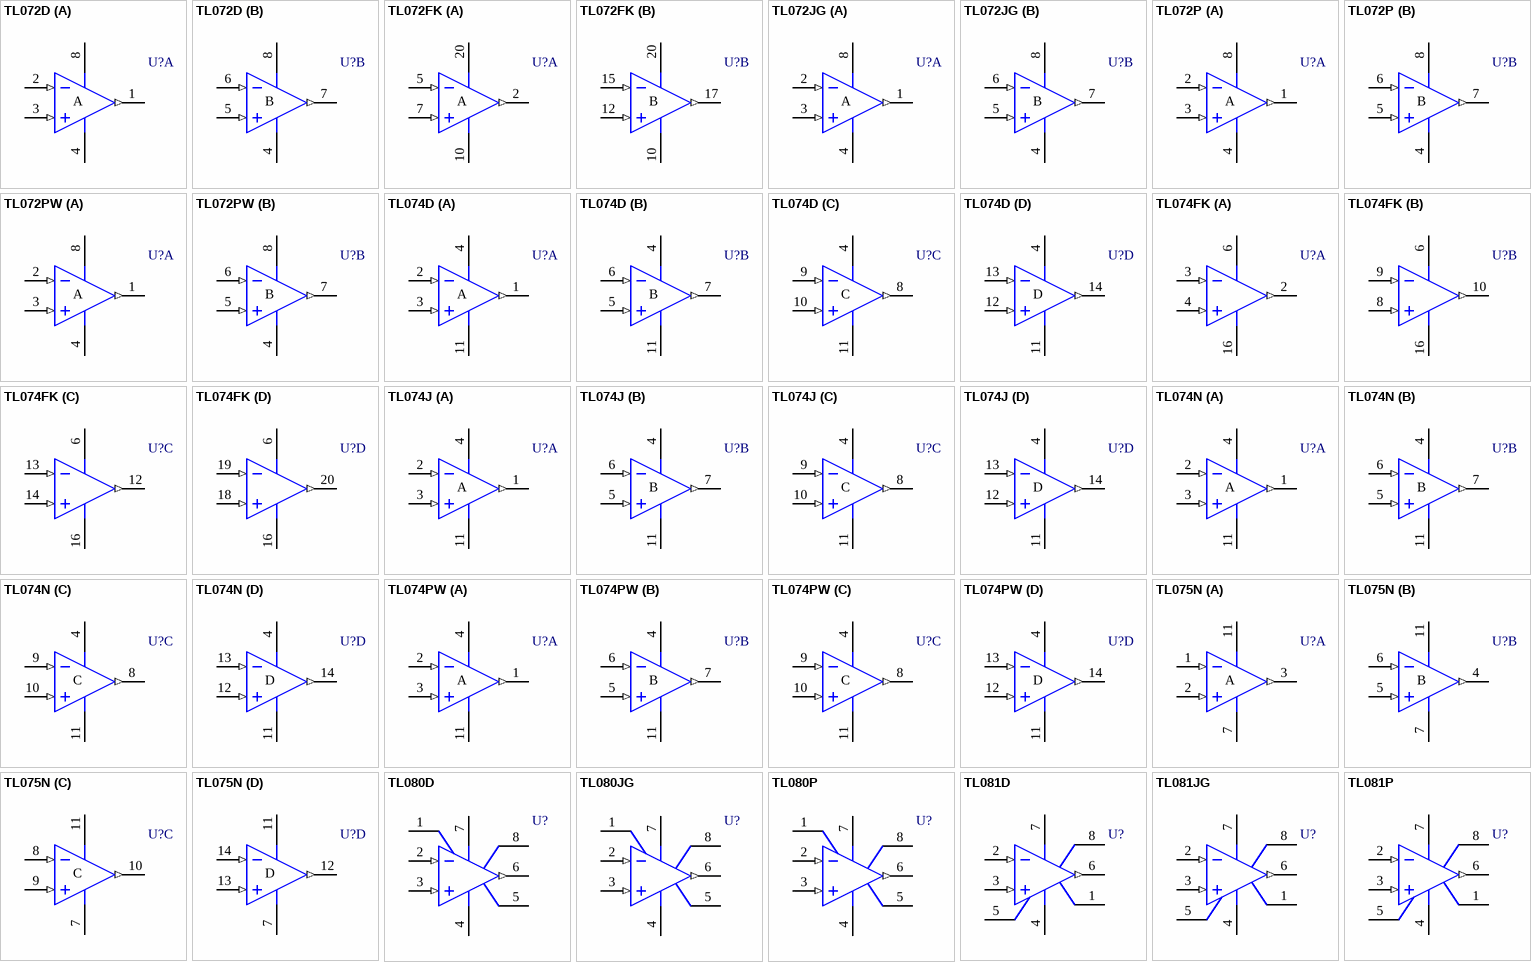
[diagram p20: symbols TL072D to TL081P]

## TL072D
designator U?
Low-Noise JFET-Input Operational Amplifier
footprint D008_L (SOIC, 8-Leads, Body 4.9x3.9mm, Pitch 1.27mm, IPC High Density)
footprint D008_M (SOIC, 8-Leads, Body 4.9x3.9mm, Pitch 1.27mm, IPC Low Density)
footprint D008_M (SOIC, 8-Leads, Body 4.9x3.9mm, Pitch 1.27mm, IPC Low Density)
3D model D008 (8-Pin Small Outline Integrated Circuit 1.27 mm Pitch)
simulation model TL072 (SUBCKT)
pins on every part: 4 V- (power), 8 V+ (power)
part A pins: 1 OUT (out), 2 IN- (in), 3 IN+ (in)
part B pins: 5 IN+ (in), 6 IN- (in), 7 OUT (out)

## TL072FK
designator U?
Low-Noise JFET-Input Operational Amplifier; Note: Pins 1,3,4,6,8,9,11,13,14,16,18 and 19 are not connected or drawn
footprint FK020 (Leadless Chip Carrier; 20 Terminals; Body 8.9 x 8.9 mm)
simulation model TL072 (SUBCKT)
pins on every part: 10 V- (power), 20 V+ (power)
part A pins: 2 OUT (out), 5 IN- (in), 7 IN+ (in)
part B pins: 12 IN+ (in), 15 IN- (in), 17 OUT (out)

## TL072JG
designator U?
Low-Noise JFET-Input Operational Amplifier
footprint JG008 (DIP; 8 Leads; Row Spacing 7.62 mm; Pitch 2.54 mm)
3D model JG008 (DIP; 8 Leads; Row Spacing 7.62 mm; Pitch 2.54 mm)
simulation model TL072 (SUBCKT)
pins on every part: 4 V- (power), 8 V+ (power)
part A pins: 1 OUT (out), 2 IN- (in), 3 IN+ (in)
part B pins: 5 IN+ (in), 6 IN- (in), 7 OUT (out)

## TL072P
designator U?
Low-Noise JFET-Input Operational Amplifier
footprint P008 (DIP; 8 Leads; Row Spacing 7.62 mm; Pitch 2.54 mm)
3D model P008 (DIP; 8 Leads; Row Spacing 7.62 mm; Pitch 2.54 mm)
simulation model TL072 (SUBCKT)
pins on every part: 4 V- (power), 8 V+ (power)
part A pins: 1 OUT (out), 2 IN- (in), 3 IN+ (in)
part B pins: 5 IN+ (in), 6 IN- (in), 7 OUT (out)

## TL072PW
designator U?
Low-Noise JFET-Input Operational Amplifier
footprint PW008_N (SOP, 8-Leads, Body 3x4.4mm, Pitch 0.65mm, IPC Medium Density)
footprint PW008_L (SOP, 8-Leads, Body 3x4.4mm, Pitch 0.65mm, IPC High Density)
footprint PW008_M (SOP, 8-Leads, Body 3x4.4mm, Pitch 0.65mm, IPC Low Density)
3D model PW008 (8-Pin Small Outline Package 0.65 mm Pitch)
simulation model TL072 (SUBCKT)
pins on every part: 4 V- (power), 8 V+ (power)
part A pins: 1 OUT (out), 2 IN- (in), 3 IN+ (in)
part B pins: 5 IN+ (in), 6 IN- (in), 7 OUT (out)

## TL074D
designator U?
Low-Noise JFET-Input Operational Amplifier
footprint D014_N (SOIC, 14-Leads, Body 8.7x3.9mm, Pitch 1.27mm, IPC Medium Density)
footprint D014_L (SOIC, 14-Leads, Body 8.7x3.9mm, Pitch 1.27mm, IPC High Density)
footprint D014_M (SOIC, 14-Leads, Body 8.7x3.9mm, Pitch 1.27mm, IPC Low Density)
3D model D014 (14-Pin Small Outline Integrated Circuit 1.27 mm Pitch)
simulation model TL074 (SUBCKT)
pins on every part: 4 V+ (power), 11 V- (power)
part A pins: 1 OUT (out), 2 IN- (in), 3 IN+ (in)
part B pins: 5 IN+ (in), 6 IN- (in), 7 OUT (out)
part C pins: 8 OUT (out), 9 IN- (in), 10 IN+ (in)
part D pins: 12 IN+ (in), 13 IN- (in), 14 OUT (out)

## TL074FK
designator U?
Low-Noise JFET-Input Operational Amplifier; Note: Pins 1,5,7,11,15 and 17 are not connected and not drawn
footprint FK020 (Leadless Chip Carrier; 20 Terminals; Body 8.9 x 8.9 mm)
simulation model TL074 (SUBCKT)
pins on every part: 6 V+ (power), 16 V- (power)
part A pins: 2 OUT (out), 3 IN- (in), 4 IN+ (in)
part B pins: 8 IN+ (in), 9 IN- (in), 10 OUT (out)
part C pins: 12 OUT (out), 13 IN- (in), 14 IN+ (in)
part D pins: 18 IN+ (in), 19 IN- (in), 20 OUT (out)

## TL074J
designator U?
Low-Noise JFET-Input Operational Amplifier
footprint J014 (DIP; 14 Leads; Row Spacing 7.62 mm; Pitch 2.54 mm)
3D model J014 (DIP; 14 Leads; Row Spacing 7.62 mm; Pitch 2.54 mm)
simulation model TL074 (SUBCKT)
pins on every part: 4 V+ (power), 11 V- (power)
part A pins: 1 OUT (out), 2 IN- (in), 3 IN+ (in)
part B pins: 5 IN+ (in), 6 IN- (in), 7 OUT (out)
part C pins: 8 OUT (out), 9 IN- (in), 10 IN+ (in)
part D pins: 12 IN+ (in), 13 IN- (in), 14 OUT (out)

## TL074N
designator U?
Low-Noise JFET-Input Operational Amplifier
footprint N014 (DIP; 14 Leads; Row Spacing 7.62 mm; Pitch 2.54 mm)
3D model N014 (DIP; 14 Leads; Row Spacing 7.62 mm; Pitch 2.54 mm)
simulation model TL074 (SUBCKT)
pins on every part: 4 V+ (power), 11 V- (power)
part A pins: 1 OUT (out), 2 IN- (in), 3 IN+ (in)
part B pins: 5 IN+ (in), 6 IN- (in), 7 OUT (out)
part C pins: 8 OUT (out), 9 IN- (in), 10 IN+ (in)
part D pins: 12 IN+ (in), 13 IN- (in), 14 OUT (out)

## TL074PW
designator U?
Low-Noise JFET-Input Operational Amplifier
footprint PW014_N (TSOP, 14-Leads, Body 5x4.4mm, Pitch 0.65mm, IPC Medium Density)
footprint PW014_L (TSOP, 14-Leads, Body 5x4.4mm, Pitch 0.65mm, IPC High Density)
footprint PW014_M (TSOP, 14-Leads, Body 5x4.4mm, Pitch 0.65mm, IPC Low Density)
3D model PW014 (14-Pin Thin Small Outline Package 0.65 mm Pitch)
simulation model TL074 (SUBCKT)
pins on every part: 4 V+ (power), 11 V- (power)
part A pins: 1 OUT (out), 2 IN- (in), 3 IN+ (in)
part B pins: 5 IN+ (in), 6 IN- (in), 7 OUT (out)
part C pins: 8 OUT (out), 9 IN- (in), 10 IN+ (in)
part D pins: 12 IN+ (in), 13 IN- (in), 14 OUT (out)

## TL075N
designator U?
Low-Noise Operational Amplifier
footprint N014 (DIP; 14 Leads; Row Spacing 7.62 mm; Pitch 2.54 mm)
3D model N014 (DIP; 14 Leads; Row Spacing 7.62 mm; Pitch 2.54 mm)
simulation model TL075 (SUBCKT)
pins on every part: 7 V- (power), 11 V+ (power)
part A pins: 1 IN- (in), 2 IN+ (in), 3 OUT (out)
part B pins: 4 OUT (out), 5 IN+ (in), 6 IN- (in)
part C pins: 8 IN- (in), 9 IN+ (in), 10 OUT (out)
part D pins: 12 OUT (out), 13 IN+ (in), 14 IN- (in)

## TL080D
designator U?
JFET-Input Operational Amplifier
footprint D008_L (SOIC, 8-Leads, Body 4.9x3.9mm, Pitch 1.27mm, IPC High Density)
footprint D008_M (SOIC, 8-Leads, Body 4.9x3.9mm, Pitch 1.27mm, IPC Low Density)
footprint D008_M (SOIC, 8-Leads, Body 4.9x3.9mm, Pitch 1.27mm, IPC Low Density)
3D model D008 (8-Pin Small Outline Integrated Circuit 1.27 mm Pitch)
simulation model TL080 (SUBCKT)
pins: 1 BAL1/CMPEN, 2 IN- (in), 3 IN+ (in), 4 V- (power), 5 BAL2, 6 OUT (out), 7 V+ (power), 8 CMPEN

## TL080JG
designator U?
JFET-Input Operational Amplifier
footprint JG008 (DIP; 8 Leads; Row Spacing 7.62 mm; Pitch 2.54 mm)
3D model JG008 (DIP; 8 Leads; Row Spacing 7.62 mm; Pitch 2.54 mm)
simulation model TL080 (SUBCKT)
pins: 1 BAL1/CMPEN, 2 IN- (in), 3 IN+ (in), 4 V- (power), 5 BAL2, 6 OUT (out), 7 V+ (power), 8 CMPEN

## TL080P
designator U?
JFET-Input Operational Amplifier
footprint P008 (DIP; 8 Leads; Row Spacing 7.62 mm; Pitch 2.54 mm)
3D model P008 (DIP; 8 Leads; Row Spacing 7.62 mm; Pitch 2.54 mm)
simulation model TL080 (SUBCKT)
pins: 1 BAL1/CMPEN, 2 IN- (in), 3 IN+ (in), 4 V- (power), 5 BAL2, 6 OUT (out), 7 V+ (power), 8 CMPEN

## TL081D
designator U?
JFET-Input Operational Amplifier; Note: Pin 8 is not connected
footprint D008_L (SOIC, 8-Leads, Body 4.9x3.9mm, Pitch 1.27mm, IPC High Density)
footprint D008_M (SOIC, 8-Leads, Body 4.9x3.9mm, Pitch 1.27mm, IPC Low Density)
footprint D008_M (SOIC, 8-Leads, Body 4.9x3.9mm, Pitch 1.27mm, IPC Low Density)
3D model D008 (8-Pin Small Outline Integrated Circuit 1.27 mm Pitch)
simulation model TL081 (SUBCKT)
pins: 1 OS TRIM, 2 IN- (in), 3 IN+ (in), 4 V- (power), 5 OS TRIM, 6 OUT (out), 7 V+ (power), 8 NC

## TL081JG
designator U?
JFET-Input Operational Amplifier; Note: Pin 8 is not connected
footprint JG008 (DIP; 8 Leads; Row Spacing 7.62 mm; Pitch 2.54 mm)
3D model JG008 (DIP; 8 Leads; Row Spacing 7.62 mm; Pitch 2.54 mm)
simulation model TL081 (SUBCKT)
pins: 1 OS TRIM, 2 IN- (in), 3 IN+ (in), 4 V- (power), 5 OS TRIM, 6 OUT (out), 7 V+ (power), 8 NC

## TL081P
designator U?
JFET-Input Operational Amplifier; Note: Pin 8 is not connected
footprint P008 (DIP; 8 Leads; Row Spacing 7.62 mm; Pitch 2.54 mm)
3D model P008 (DIP; 8 Leads; Row Spacing 7.62 mm; Pitch 2.54 mm)
simulation model TL081 (SUBCKT)
pins: 1 OS TRIM, 2 IN- (in), 3 IN+ (in), 4 V- (power), 5 OS TRIM, 6 OUT (out), 7 V+ (power), 8 NC

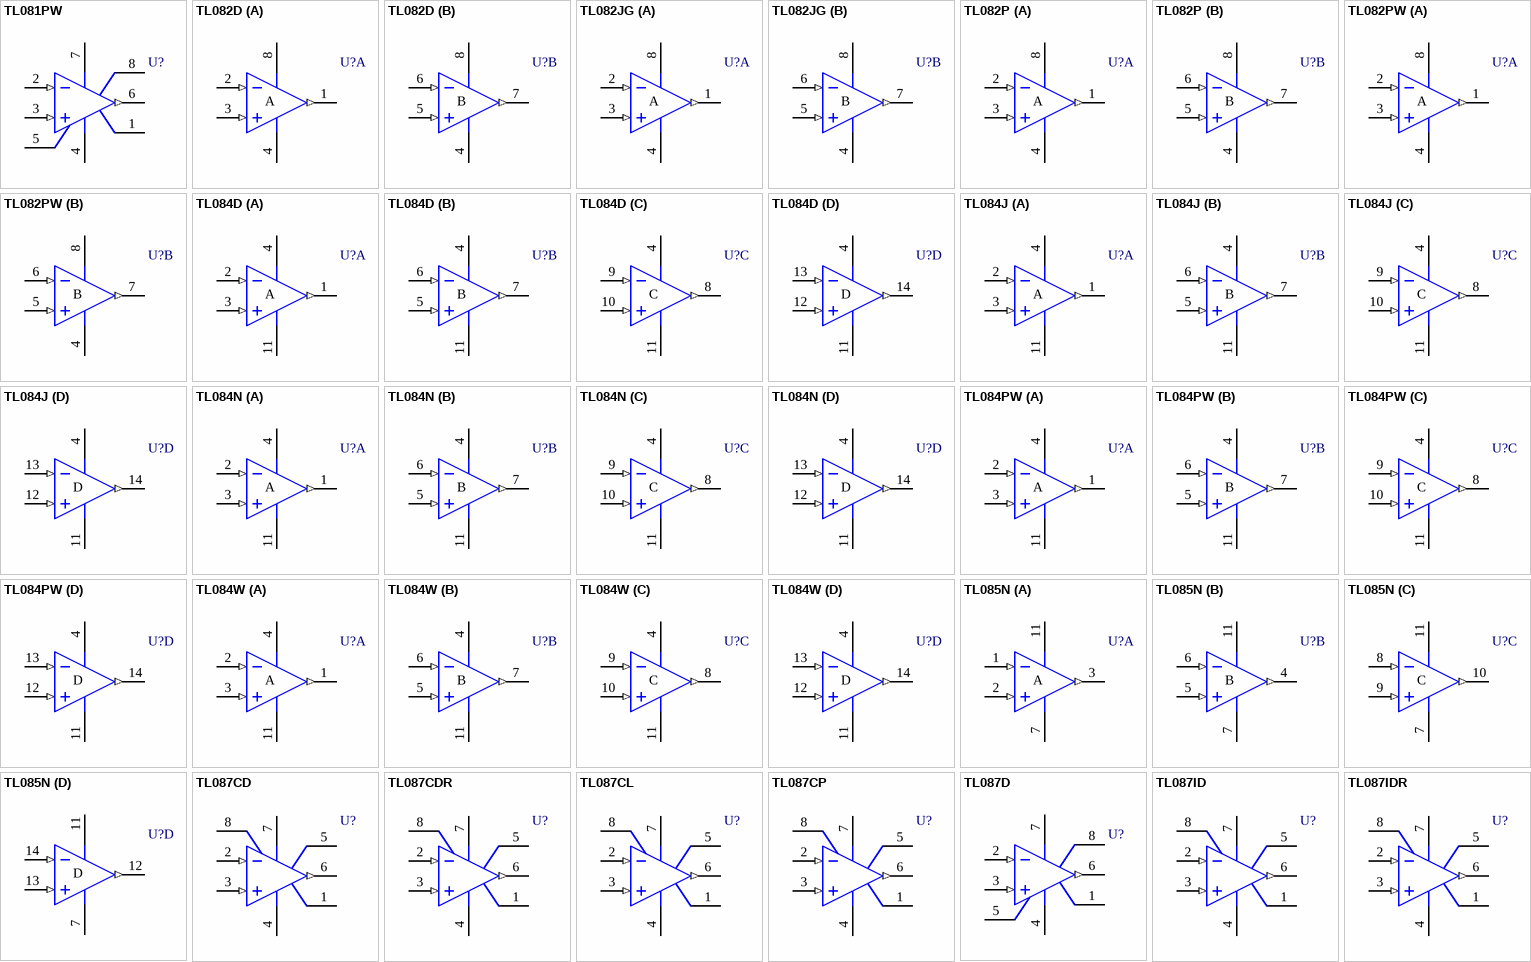
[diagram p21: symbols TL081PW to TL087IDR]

## TL081PW
designator U?
JFET-Input Operational Amplifier; Note: Pin 8 is not connected
footprint PW008_N (SOP, 8-Leads, Body 3x4.4mm, Pitch 0.65mm, IPC Medium Density)
footprint PW008_L (SOP, 8-Leads, Body 3x4.4mm, Pitch 0.65mm, IPC High Density)
footprint PW008_M (SOP, 8-Leads, Body 3x4.4mm, Pitch 0.65mm, IPC Low Density)
3D model PW008 (8-Pin Small Outline Package 0.65 mm Pitch)
simulation model TL081 (SUBCKT)
pins: 1 OS TRIM, 2 IN- (in), 3 IN+ (in), 4 V- (power), 5 OS TRIM, 6 OUT (out), 7 V+ (power), 8 NC

## TL082D
designator U?
JFET-Input Operational Amplifier
footprint D008_L (SOIC, 8-Leads, Body 4.9x3.9mm, Pitch 1.27mm, IPC High Density)
footprint D008_M (SOIC, 8-Leads, Body 4.9x3.9mm, Pitch 1.27mm, IPC Low Density)
footprint D008_M (SOIC, 8-Leads, Body 4.9x3.9mm, Pitch 1.27mm, IPC Low Density)
3D model D008 (8-Pin Small Outline Integrated Circuit 1.27 mm Pitch)
simulation model TL082 (SUBCKT)
pins on every part: 4 V- (power), 8 V+ (power)
part A pins: 1 OUT (out), 2 IN- (in), 3 IN+ (in)
part B pins: 5 IN+ (in), 6 IN- (in), 7 OUT (out)

## TL082JG
designator U?
JFET-Input Operational Amplifier
footprint JG008 (DIP; 8 Leads; Row Spacing 7.62 mm; Pitch 2.54 mm)
3D model JG008 (DIP; 8 Leads; Row Spacing 7.62 mm; Pitch 2.54 mm)
simulation model TL082 (SUBCKT)
pins on every part: 4 V- (power), 8 V+ (power)
part A pins: 1 OUT (out), 2 IN- (in), 3 IN+ (in)
part B pins: 5 IN+ (in), 6 IN- (in), 7 OUT (out)

## TL082P
designator U?
JFET-Input Operational Amplifier
footprint P008 (DIP; 8 Leads; Row Spacing 7.62 mm; Pitch 2.54 mm)
3D model P008 (DIP; 8 Leads; Row Spacing 7.62 mm; Pitch 2.54 mm)
simulation model TL082 (SUBCKT)
pins on every part: 4 V- (power), 8 V+ (power)
part A pins: 1 OUT (out), 2 IN- (in), 3 IN+ (in)
part B pins: 5 IN+ (in), 6 IN- (in), 7 OUT (out)

## TL082PW
designator U?
JFET-Input Operational Amplifier
footprint PW008_N (SOP, 8-Leads, Body 3x4.4mm, Pitch 0.65mm, IPC Medium Density)
footprint PW008_L (SOP, 8-Leads, Body 3x4.4mm, Pitch 0.65mm, IPC High Density)
footprint PW008_M (SOP, 8-Leads, Body 3x4.4mm, Pitch 0.65mm, IPC Low Density)
3D model PW008 (8-Pin Small Outline Package 0.65 mm Pitch)
simulation model TL082 (SUBCKT)
pins on every part: 4 V- (power), 8 V+ (power)
part A pins: 1 OUT (out), 2 IN- (in), 3 IN+ (in)
part B pins: 5 IN+ (in), 6 IN- (in), 7 OUT (out)

## TL084D
designator U?
JFET-Input Operational Amplifier
footprint D014_N (SOIC, 14-Leads, Body 8.7x3.9mm, Pitch 1.27mm, IPC Medium Density)
footprint D014_L (SOIC, 14-Leads, Body 8.7x3.9mm, Pitch 1.27mm, IPC High Density)
footprint D014_M (SOIC, 14-Leads, Body 8.7x3.9mm, Pitch 1.27mm, IPC Low Density)
3D model D014 (14-Pin Small Outline Integrated Circuit 1.27 mm Pitch)
simulation model TL084 (SUBCKT)
pins on every part: 4 V+ (power), 11 V- (power)
part A pins: 1 OUT (out), 2 IN- (in), 3 IN+ (in)
part B pins: 5 IN+ (in), 6 IN- (in), 7 OUT (out)
part C pins: 8 OUT (out), 9 IN- (in), 10 IN+ (in)
part D pins: 12 IN+ (in), 13 IN- (in), 14 OUT (out)

## TL084J
designator U?
JFET-Input Operational Amplifier
footprint J014 (DIP; 14 Leads; Row Spacing 7.62 mm; Pitch 2.54 mm)
3D model J014 (DIP; 14 Leads; Row Spacing 7.62 mm; Pitch 2.54 mm)
simulation model TL084 (SUBCKT)
pins on every part: 4 V+ (power), 11 V- (power)
part A pins: 1 OUT (out), 2 IN- (in), 3 IN+ (in)
part B pins: 5 IN+ (in), 6 IN- (in), 7 OUT (out)
part C pins: 8 OUT (out), 9 IN- (in), 10 IN+ (in)
part D pins: 12 IN+ (in), 13 IN- (in), 14 OUT (out)

## TL084N
designator U?
JFET-Input Operational Amplifier
footprint N014 (DIP; 14 Leads; Row Spacing 7.62 mm; Pitch 2.54 mm)
3D model N014 (DIP; 14 Leads; Row Spacing 7.62 mm; Pitch 2.54 mm)
simulation model TL084 (SUBCKT)
pins on every part: 4 V+ (power), 11 V- (power)
part A pins: 1 OUT (out), 2 IN- (in), 3 IN+ (in)
part B pins: 5 IN+ (in), 6 IN- (in), 7 OUT (out)
part C pins: 8 OUT (out), 9 IN- (in), 10 IN+ (in)
part D pins: 12 IN+ (in), 13 IN- (in), 14 OUT (out)

## TL084PW
designator U?
JFET-Input Operational Amplifier
footprint PW014_N (TSOP, 14-Leads, Body 5x4.4mm, Pitch 0.65mm, IPC Medium Density)
footprint PW014_L (TSOP, 14-Leads, Body 5x4.4mm, Pitch 0.65mm, IPC High Density)
footprint PW014_M (TSOP, 14-Leads, Body 5x4.4mm, Pitch 0.65mm, IPC Low Density)
3D model PW014 (14-Pin Thin Small Outline Package 0.65 mm Pitch)
simulation model TL084 (SUBCKT)
pins on every part: 4 V+ (power), 11 V- (power)
part A pins: 1 OUT (out), 2 IN- (in), 3 IN+ (in)
part B pins: 5 IN+ (in), 6 IN- (in), 7 OUT (out)
part C pins: 8 OUT (out), 9 IN- (in), 10 IN+ (in)
part D pins: 12 IN+ (in), 13 IN- (in), 14 OUT (out)

## TL084W
designator U?
JFET-Input Operational Amplifier
footprint W014 (DFP; 14 Leads; Body 9.9 x 6.6 mm (LxW max); Pitch 1.27 mm)
3D model W014 (DFP; 14 Leads; Body 9.9 x 6.6 mm (LxW max); Pitch 1.27 mm)
simulation model TL084 (SUBCKT)
pins on every part: 4 V+ (power), 11 V- (power)
part A pins: 1 OUT (out), 2 IN- (in), 3 IN+ (in)
part B pins: 5 IN+ (in), 6 IN- (in), 7 OUT (out)
part C pins: 8 OUT (out), 9 IN- (in), 10 IN+ (in)
part D pins: 12 IN+ (in), 13 IN- (in), 14 OUT (out)

## TL085N
designator U?
JFET-Input Operational Amplifier
footprint N014 (DIP; 14 Leads; Row Spacing 7.62 mm; Pitch 2.54 mm)
3D model N014 (DIP; 14 Leads; Row Spacing 7.62 mm; Pitch 2.54 mm)
simulation model TL085 (SUBCKT)
pins on every part: 7 V- (power), 11 V+ (power)
part A pins: 1 IN- (in), 2 IN+ (in), 3 OUT (out)
part B pins: 4 OUT (out), 5 IN+ (in), 6 IN- (in)
part C pins: 8 IN- (in), 9 IN+ (in), 10 OUT (out)
part D pins: 12 OUT (out), 13 IN+ (in), 14 IN- (in)

## TL087CD
designator U?
JFET-Input Operational Amplifier; ComponentAvailability: Obsolete
footprint D008_L (SOIC, 8-Leads, Body 4.9x3.9mm, Pitch 1.27mm, IPC High Density)
footprint D008_M (SOIC, 8-Leads, Body 4.9x3.9mm, Pitch 1.27mm, IPC Low Density)
footprint D008_M (SOIC, 8-Leads, Body 4.9x3.9mm, Pitch 1.27mm, IPC Low Density)
3D model D008 (8-Pin Small Outline Integrated Circuit 1.27 mm Pitch)
pins: 1 OS N1, 2 IN- (in), 3 IN+ (in), 4 V- (power), 5 OS N2, 6 OUT (out), 7 V+ (power), 8 NC

## TL087CDR
designator U?
JFET-Input Operational Amplifier; ComponentAvailability: Obsolete
footprint D008_L (SOIC, 8-Leads, Body 4.9x3.9mm, Pitch 1.27mm, IPC High Density)
footprint D008_M (SOIC, 8-Leads, Body 4.9x3.9mm, Pitch 1.27mm, IPC Low Density)
footprint D008_M (SOIC, 8-Leads, Body 4.9x3.9mm, Pitch 1.27mm, IPC Low Density)
3D model D008 (8-Pin Small Outline Integrated Circuit 1.27 mm Pitch)
pins: 1 OS N1, 2 IN- (in), 3 IN+ (in), 4 V- (power), 5 OS N2, 6 OUT (out), 7 V+ (power), 8 NC

## TL087CL
designator U?
JFET-Input Operational Amplifier; Note: Pin 4 is in electrical contact with the case; ComponentAvailability: Obsolete
footprint L008 (Can; 8 Leads; Pin Circle Dia. 5.08 mm; Lead Dia. 0.48 mm (max))
pins: 1 OS N1, 2 IN- (in), 3 IN+ (in), 4 V- (power), 5 OS N2, 6 OUT (out), 7 V+ (power), 8 NC

## TL087CP
designator U?
JFET-Input Operational Amplifier; ComponentAvailability: Obsolete
footprint P008 (DIP; 8 Leads; Row Spacing 7.62 mm; Pitch 2.54 mm)
3D model P008 (DIP; 8 Leads; Row Spacing 7.62 mm; Pitch 2.54 mm)
pins: 1 OS N1, 2 IN- (in), 3 IN+ (in), 4 V- (power), 5 OS N2, 6 OUT (out), 7 V+ (power), 8 NC

## TL087D
designator U?
JFET-Input Operational Amplifier; Note: Pin 8 is not connected
footprint D008_L (SOIC, 8-Leads, Body 4.9x3.9mm, Pitch 1.27mm, IPC High Density)
footprint D008_M (SOIC, 8-Leads, Body 4.9x3.9mm, Pitch 1.27mm, IPC Low Density)
footprint D008_M (SOIC, 8-Leads, Body 4.9x3.9mm, Pitch 1.27mm, IPC Low Density)
3D model D008 (8-Pin Small Outline Integrated Circuit 1.27 mm Pitch)
simulation model TL087 (SUBCKT)
pins: 1 OS TRIM, 2 IN- (in), 3 IN+ (in), 4 V- (power), 5 OS TRIM, 6 OUT (out), 7 V+ (power), 8 NC

## TL087ID
designator U?
JFET-Input Operational Amplifier; ComponentAvailability: Obsolete
footprint D008_L (SOIC, 8-Leads, Body 4.9x3.9mm, Pitch 1.27mm, IPC High Density)
footprint D008_M (SOIC, 8-Leads, Body 4.9x3.9mm, Pitch 1.27mm, IPC Low Density)
footprint D008_M (SOIC, 8-Leads, Body 4.9x3.9mm, Pitch 1.27mm, IPC Low Density)
3D model D008 (8-Pin Small Outline Integrated Circuit 1.27 mm Pitch)
pins: 1 OS N1, 2 IN- (in), 3 IN+ (in), 4 V- (power), 5 OS N2, 6 OUT (out), 7 V+ (power), 8 NC

## TL087IDR
designator U?
JFET-Input Operational Amplifier; ComponentAvailability: Obsolete
footprint D008_L (SOIC, 8-Leads, Body 4.9x3.9mm, Pitch 1.27mm, IPC High Density)
footprint D008_M (SOIC, 8-Leads, Body 4.9x3.9mm, Pitch 1.27mm, IPC Low Density)
footprint D008_M (SOIC, 8-Leads, Body 4.9x3.9mm, Pitch 1.27mm, IPC Low Density)
3D model D008 (8-Pin Small Outline Integrated Circuit 1.27 mm Pitch)
pins: 1 OS N1, 2 IN- (in), 3 IN+ (in), 4 V- (power), 5 OS N2, 6 OUT (out), 7 V+ (power), 8 NC

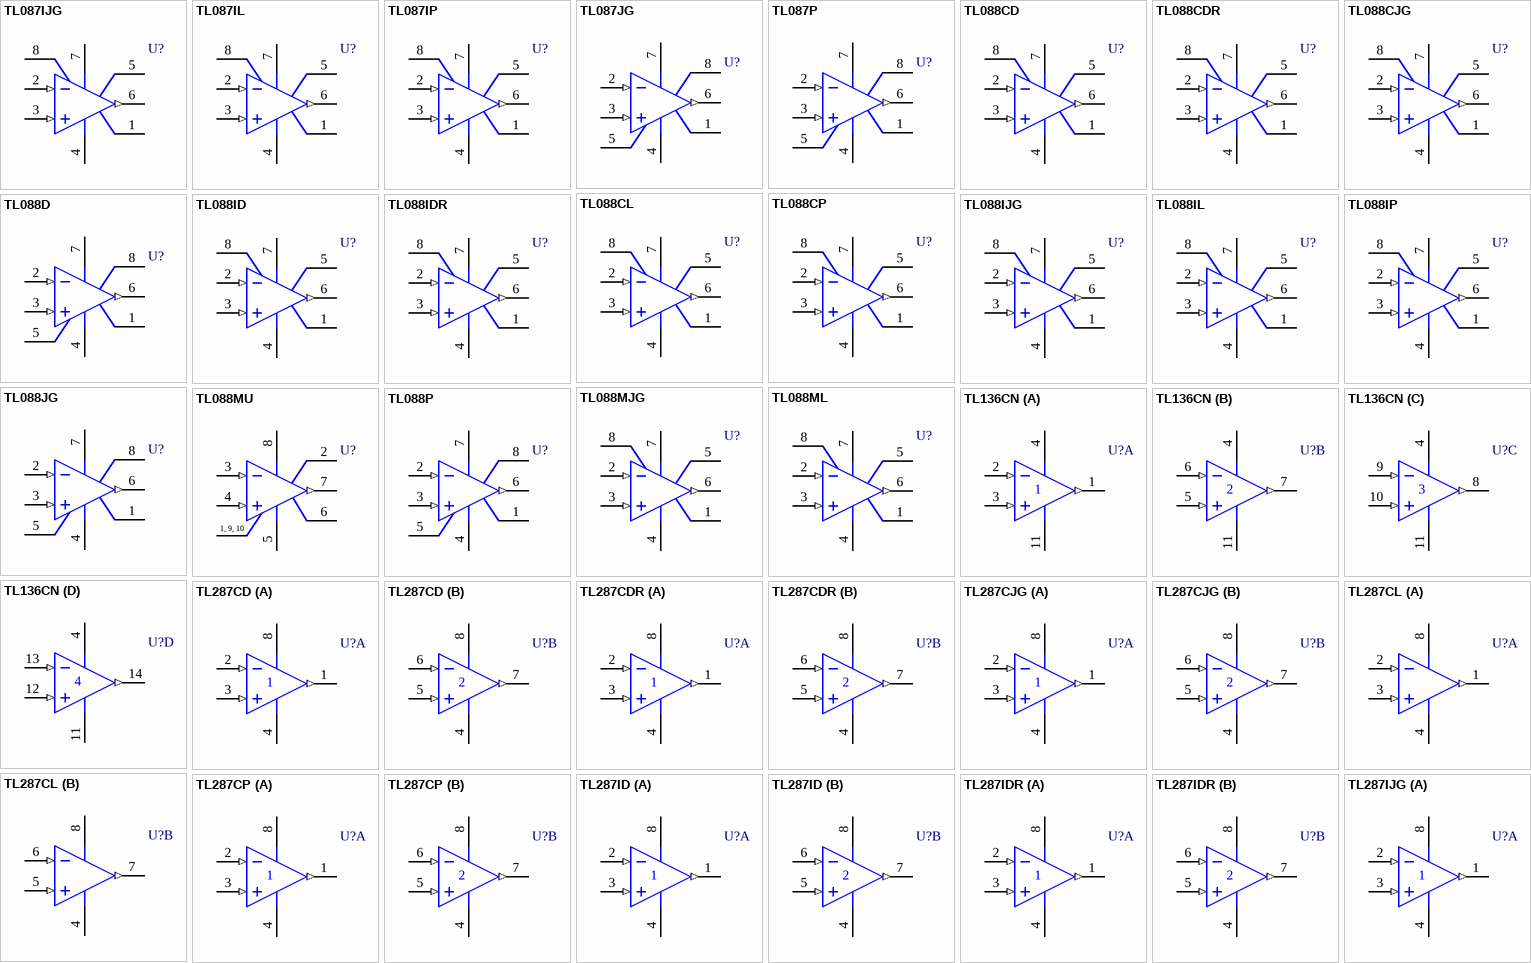
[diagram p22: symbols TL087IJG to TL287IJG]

## TL087IJG
designator U?
JFET-Input Operational Amplifier; ComponentAvailability: Obsolete
footprint JG008 (DIP; 8 Leads; Row Spacing 7.62 mm; Pitch 2.54 mm)
3D model JG008 (DIP; 8 Leads; Row Spacing 7.62 mm; Pitch 2.54 mm)
pins: 1 OS N1, 2 IN- (in), 3 IN+ (in), 4 V- (power), 5 OS N2, 6 OUT (out), 7 V+ (power), 8 NC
